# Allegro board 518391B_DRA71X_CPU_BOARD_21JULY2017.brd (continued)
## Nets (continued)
I2C4_SDA: R173.1 R178.1 U30.9(SDA) U33.1(I2C_SDA)
ICLINK_01_0: U34.43(ICP) U36.35(NVMISO)
ICLINK_01_1: U34.42(ICN) U36.36(NVMOSI)
ICLINK_01_2: U34.41(DIFSO) U36.37(VSSB)
ICLINK_01_3: U34.40(DICLKO) U36.38(NVSCLK)
IRQ_GNSS: U21.49(IRQ_GNSS) U27.Y1(MMC3_CMD/SPI3_SCLK/USB3_ULPI_D4)
ISFSN_CHIP_01: U34.32(ISFSN) U36.52(ISFSN)
ISFSP_CHIP_01: U34.33(ISFSP) U36.53(ISFSP)
LDOVANA: C458.1 U32.43(LDOVANA_OUT)
LDRV1: R20.2 U19.25(LDRV1)
LDRV2: R21.1 U19.21(LDRV2)
LIN_INH: TP53.1 U47.8(INH)
LIN_WAKE: TP48.1 U47.3(NWAKE)
MCU_CAN0_RX: U37.62(P10_0) U46.4(RXD)
MCU_CAN0_STB: R383.1 U37.29(P8_3) U46.8(STB)
MCU_CAN0_TX: U37.63(P10_1) U46.1(TXD)
MCU_CAN2_RX: RJ27.1 U37.10(P0_5)
MCU_CAN2_STB: RJ31.1 U37.28(P8_1)
MCU_CAN2_TX: RJ28.1 U37.9(P0_4)
MCU_DBG_RESETN: J15.13 R349.2
MCU_DCAN1_RX: R371.2 RJ27.3
MCU_DCAN1_STB: R426.2 RJ31.3
MCU_DCAN1_TX: R372.2 RJ28.3
MCU_FLMD0: J15.4 R332.1 U37.26(FLMD0)
MCU_FLMD1: J15.6 R322.1 R323.2
MCU_LIN_EN: R375.1 U37.30(P8_4) U47.2(EN)
MCU_P10_9: R327.2 U37.54(P10_9)
MCU_P10_10: R331.2 U37.55(P10_10)
MCU_P10_13: R335.2 U37.58(P10_13)
MCU_P10_14: R341.2 U37.59(P10_14)
MCU_PMIC_POWERHOLD: Q2.5(G2) R319.2 U37.31(P8_5)
MCU_RDY: J15.11 U37.14(JP0_5)
MCU_RESETN: C498.2 R345.1 R349.1 U37.20(RESET)
MCU_RLIN30RX: R356.2 U37.7(P0_3)
MCU_RLIN30TX: R357.2 U37.6(P0_2)
MCU_RLIN31RX: R374.2 U37.56(P10_11) U47.1(RXD)
MCU_RLIN31TX: U37.57(P10_12) U47.4(TXD)
MCU_SCL: R350.2 U37.1(P10_3) U38.6(SCL)
MCU_SDA: R351.2 U37.64(P10_2) U38.5(SDA)
MCU_SPI1_SI: R323.1 U37.53(P10_8)
MCU_TCK: J15.1 U37.17(JP0_2)
MCU_TDI: J15.7 R348.2 U37.19(JP0_0)
MCU_TDO: J15.5 U37.18(JP0_1)
MCU_TMS: R354.2 R391.1 U37.16(JP0_3)
MCU_TRSTN: R355.1 R377.1 U37.15(JP0_4)
MCU_TVD: J15.8 R376.1
MCU_WP: R347.1 U37.27(P8_0) U38.7(WP)
MCU_X1: C493.1 U37.25(X1) X1.2
MCU_X2: R130.2 U37.24(X2)
MDIO_MDCLK: U27.D10(VIN2A_D10/MDIO_MCLK/VOUT2_D13/K) U40.1(MDC)
MDIO_MDIO: R344.2 U27.C10(VIN2A_D11/MDIO_D/VOUT2_D12/KBD_) U40.36(MDIO)
MMC2_CLK: R99.1 R299.1 R300.2
MMC2_CMD: R295.2 U27.A6(GPMC_CS1/MMC2_CMD/GPMC_A22/VIN2) U31.P5(CMD)
MMC2_DAT0: R273.2 U27.D7(GPMC_A24/MMC2_DAT0/GPMC_A18/VIN) U31.K2(DAT0)
MMC2_DAT1: R271.2 U27.C6(GPMC_A25/MMC2_DAT1/GPMC_A19/VIN) U31.N2(DAT1)
MMC2_DAT2: R269.2 U27.A5(GPMC_A26/MMC2_DAT2/GPMC_A20/VIN) U31.K3(DAT2)
MMC2_DAT3: R291.2 U27.B6(GPMC_A27/MMC2_DAT3/GPMC_A21/VIN) U31.N3(DAT3)
MMC2_DAT4: R289.2 U27.A4(GPMC_A19/MMC2_DAT4/GPMC_A13/VIN) U31.N8(DAT4)
MMC2_DAT5: R272.2 U27.E7(GPMC_A20/MMC2_DAT5/GPMC_A14/VIN) U31.K8(DAT5)
MMC2_DAT6: R270.2 U27.D6(GPMC_A21/MMC2_DAT6/GPMC_A15/VIN) U31.N9(DAT6)
MMC2_DAT7: R268.2 U27.C5(GPMC_A22/MMC2_DAT7/GPMC_A16/VIN) U31.K9(DAT7)
MMC_PWR_ON: R412.2 U27.K23(GPIO6_16/MCASP1_AXR10/CLKOUT1/T) U70.3(ON)
NEO_RESETN: R238.2 U25.8(RESET_N) U27.H3(GPMC_A13/QSPI1_RTCLK/TIMER7/SPI)
NEO_TIMEPULSE: R68.2 R69.1 R79.2
NFAULT: D11.2(C) U27.H2(GPMC_BEN0/GPMC_CS4/VIN2B_DE1/VI) U28.26(FAULTN)
NMUTE: U27.K5(GPMC_A16/QSPI1_D0(I/O)/GPIO2_6) U28.25(MUTEN)
NSTANDBY: U27.K6(GPMC_A15/QSPI1_D2(I)/TIMER5/GPI) U28.24(STANDBYN)
NTRST: J14.9(NTRST) R312.2 RJ26.3
NWARN: D10.2(C) U27.H6(GPMC_BEN1/GPMC_CS5/VIN2B_CLK1/V) U28.27(WARNN)
OUT1M: C87.1 L12.1 U28.32(OUT_1M)
OUT1P: C93.1 L13.1 U28.34(OUT_1P)
OUT2M: C330.1 L55.1 U28.38(OUT_2M)
OUT2P: C371.1 L56.1 U28.40(OUT_2P)
OUT3M: C97.1 L14.1 U28.45(OUT_3M)
OUT3P: C107.1 L15.1 U28.47(OUT_3P)
OUT4M: C376.1 L57.1 U28.51(OUT_4M)
OUT4P: C400.1 L58.1 U28.53(OUT_4P)
PG1_PMIC: R127.1 R316.1 TP41.1(TP) U32.27(GPIO_6 [VRTC])
PG_LM5141: Q11.2(G2) R217.1 SW2.3(B2) TP12.1(TP) U18.21(PG) U42.6(EN)
PG_LM5175: C63.2 R40.2 R208.1 TP9.1(TP) U19.17(PGOOD) U43.3(IN) U51.3(IN)
PG_LM53603: R7.2 TP6.1(TP) U11.7(EN) U15.8(RESETN)
PM1_SCL: J21.36 R414.1 U71.2(I) U74.5(SCL)
PM1_SDA: J21.38 R415.1 U72.2(I) U74.4(SDA)
PM_BRD_PWR_OFF: J21.26 Q11.5(G2) R423.1
PM_RESETN: J21.28 R402.2
PMIC_ADCIN1: R115.1 U32.38(ADCIN1)
PMIC_ADCIN2: R112.1 U32.39(ADCIN2)
PMIC_BOOT: R106.2 R107.2 U32.16(BOOT [VRTC])
PMIC_EN: R433.2 SW2.1(A1) SW2.2(A2) U32.15(GPIO_5 [VRTC]) U39.3(ON)
PMIC_GPIO_2: TP35.1 U32.2(GPIO_2 [VIO_IN])
PMIC_GPIO_4: TP37.1 U32.1(GPIO_4 [VIO_IN])
PMIC_POWERHOLD: Q2.3(D2) R41.1 R422.1 SW2.4(B1)
PMIC_REGEN1_3V3_OD: R378.1 TP50.1(TP) U19.1(EN/UVLO) U20.3(ON) U32.12(GPIO_0 [VRTC]) U41.5(EN) U48.3(ON) U49.5(EN)
PMIC_SCLK_OUT: TP34.1 U32.48(SYNCCLKOUT [VRTC])
SD_CLK: R406.1 RU1.14(4B1)
SD_CMD: R405.1 RU1.11(3B1)
SD_D0: R407.1 RU2.2(1B1)
SD_D1: R408.1 RU2.5(2B1)
SD_D2: R403.1 RU1.2(1B1)
SD_D3: R404.1 RU1.5(2B1)
SIL_INTB_CHIP0: R313.1 U27.F3(GPMC_CS0/GPIO2_19) U36.39(INTM)
SIL_INTB_CHIP1: R122.1 U27.G4(GPMC_CS2/QSPI1_CS0/GPIO2_20/GPM) U34.19(INTB)
SIL_RSTB_CHIP0: R320.1 U27.L3(GPMC_A11/VIN1A_FLD0/VOUT3_FLD/V) U36.33(RSTB)
SIL_RSTB_CHIP1: R126.1 U27.G1(GPMC_A12/GPMC_A0/VIN1B_FLD1/TIM) U34.13(RSTB)
SWP1: J8.1 R258.2 SW1.1(A1)
SWP2: J8.3 R254.2 SW1.2(A2)
SWP3: J8.5 R250.2 SW1.3(A3)
SWP4: J8.7 R248.2 SW1.4(A4)
SWP5: J8.9 R244.2 SW1.5(A5)
SWP6: J8.11 R240.2 SW1.6(A6)
TAS_LRCLK_2INM: C100.1 R256.1 U28.14(FSYNC)
TAS_MCLK_3INM: C104.1 RJ29.2 U28.12(MCLK)
TAS_SCLK_2INP: C99.1 R257.1 U28.13(SCLK)
TAS_SDIN1A_1INP: C94.1 R253.1 U28.15(SDIN1)
TAS_SDIN2A_1INM: C95.1 R252.1 U28.16(SDIN2)
TAS_SYNC: RJ8.3 RJ9.2
TLIN1: J17.10 R154.2 U47.6(LIN)
TRD1_N: C233.1 J17.2
TRD1_P: C232.1 J17.1
TRD_N: L44.3 U40.13(TRD_N)
TRD_P: L44.4 U40.12(TRD_P)
TRSTPD: J14.8(TRSTPD) R330.1 RJ26.1
USB1_CS: C262.1 R10.1 R203.2 R204.1
USB1_DM: FL2.1 U11.14(DM_IN)
USB1_DP: FL2.4 U11.13(DP_IN)
USB1_IMON: C18.1 R6.1 R317.2 TP3.1(TP) U11.1(IMON)
USB1_STATUS: R2.1 U11.17(STATUS) U27.K22(GPIO6_15/MCASP1_AXR9/DCAN2_RX/U)
USB1_VBUS_OCN: R3.1 U11.18(FAULT) U27.H21(GPIO6_14/MCASP1_AXR8/DCAN2_TX/U)
USB2_DM: FL1.4 U12.5(VD-)
USB2_DP: FL1.1 U12.6(VD+)
USB_AC_TXN0: C14.2 FL6.4
USB_AC_TXP0: C13.2 FL6.1
VAUDIO_9V0: C191.1 C445.1 C484.1 C510.1 C528.1 C533.1 R293.1 R304.2 R314.1 R326.2 R352.1 R364.1 R366.2 R385.1 R392.2 R395.1 R399.2 TP45.1(TP) U44.16(OUT)
VBIAS_ERR: R135.2 U27.F6(GPMC_WAIT0/GPIO2_28/GPMC_A25/GP) U44.9(ERR)
VBIAS_SNS_SEL: R384.1 U27.N5(UART3_RXD/RMII1_CRS/MII0_RXDV/V) U44.7(SNS_SEL)
VCAM_9V0: C177.1 C234.1 C249.1 L51.2 R363.1 TP46.1(TP) U44.14(OUT2)
VCAP_VBBLDO_DSP: C388.1 U27.F8(CAP_VBBLDO_DSP)
VCAP_VBBLDO_GPU: C329.1 U27.T7(CAP_VBBLDO_GPU)
VCAP_VBBLDO_IVA: C395.1 U27.G14(CAP_VBBLDO_IVA)
VCAP_VBBLDO_MPU: C394.1 U27.F17(CAP_VBBLDO_MPU)
VCAP_VDDRAM_CORE1: C322.1 U27.U20(CAP_VDDRAM_CORE1)
VCAP_VDDRAM_CORE3: C358.1 U27.K7(CAP_VDDRAM_CORE3)
VCAP_VDDRAM_CORE4: C412.1 U27.G19(CAP_VDDRAM_CORE4)
VCAP_VDDRAM_DSP: C334.1 U27.L7(CAP_VDDRAM_DSP)
VCAP_VDDRAM_GPU: C320.1 U27.V7(CAP_VDDRAM_GPU)
VCAP_VDDRAM_IVA: C426.1 U27.G12(CAP_VDDRAM_IVA)
VCAP_VDDRAM_MPU: C374.1 U27.G18(CAP_VDDRAM_MPU)
VCNTL_3V3: C481.1 Q8.3(D2) R373.2 R378.2 U32.34(VIO_IN)
VDA_COREGMACVID_FIL1V8: C359.1 C372.1 E5.3 U27.K10(VDDA_DSP_IVA_1) U27.L9(VDDA_CORE_GMAC) U27.L10(VDDA_DSP_IVA_2)
VDA_CSI_FIL1V8: C324.1 C333.1 E3.3 U27.T6(VDDA_CSI)
VDA_DDRDBGGPUPER_FIL1V8: C340.1 C343.1 E4.3 U27.M10(VDDA_PER) U27.N9(VDDA_GPU) U27.N10(VDDA_DEBUG)
VDA_MPU_ABE_FIL1V8: C349.1 C407.1 E7.3 U27.K16(VDDA_MPU_ABE_1) U27.L16(VDDA_MPU_ABE_2)
VDA_OSC_FIL1V8: C286.1 C309.1 E1.3 U27.W13(VDDA_OSC_1) U27.Y13(VDDA_OSC_2)
VDA_PCIE_FIL1V8: C301.1 C308.1 C310.1 E2.3 U27.W11(VDDA_PCIE_1) U27.W15(VDDA_HDMI_1) U27.Y11(VDDA_PCIE_2) U27.Y15(VDDA_HDMI_2)
VDA_PHY_1V8: C302.1 C306.1 C465.1 E2.1 E3.1 U27.W8(VDDA_USB_1) U27.Y8(VDDA_USB_2) U27.Y9(VDDA_USB_3) U32.21(LDO2_OUT)
VDA_PLL_1V8: C331.1 C406.1 C443.1 E1.1 E4.1 E5.1 E6.1 E7.1 U27.R20(VDDA_DDR) U32.4(LDO5_OUT)
VDA_SDIO_DV: C345.1 C477.1 R226.1 R227.1 R228.1 R229.1 R230.1 R231.1 R410.1 U27.N8(VDDSHV8_1) U27.P8(VDDSHV8_2) U32.23(LDO1_OUT)
VDA_USB_3V3: C281.1 C284.1 C285.1 C440.1 R236.2 R237.1 U27.AA10(VDDA33V_USB_1) U27.Y10(VDDA33V_USB_2) U32.7(LDO4_OUT)
VDA_VIDEO_FIL1V8: C364.1 C408.1 E6.3 U27.K14(VDDA_VIDEO_1) U27.L14(VDDA_VIDEO_2)
VDISP_16V0: C146.1 C462.1 L20.2 TP47.1(TP) U43.5(OUT5) U43.6(OUT6) U43.7(OUT7)
VEXP_1V8A: J19.113 R171.2
VEXP_1V8B: J19.112 R170.2
VEXP_3V3A: J19.8 R188.1
VEXP_3V3B: J19.9 R187.1
VEXP_5V0A: J19.1 R186.1
VEXP_5V0B: J19.5 R185.1
VEXP_5V0C: J19.117 R167.2
VEXP_5V0D: J19.116 R166.2
VHDMI_5V0: C268.1 P1.18(+5V) U17.12(5V_OUT)
VIO_3V3: C44.1 C49.1 C57.1 C83.1 C114.1 C118.1 C119.1 C120.1 C128.1 C136.1 C137.1 C140.1 C141.1 C147.1 C148.1 C151.1 C152.1 C189.1 C207.1 C212.1 C260.1 C261.1 C264.1 C267.1 C275.2 C277.1 C282.1 C283.1 C287.1 C288.1 C296.1 C350.1 C353.1 C356.1 C435.1 C437.1 C442.2 C446.2 C451.1 C453.1 C455.2 C456.2 C457.2 C459.1 C461.1 C507.1 C508.1 C509.1 C511.1 C517.1 C518.1 C519.1 C539.2 C546.1 J21.1 J21.2 J21.3 L16.1 L17.2 L63.1 P9.30 P9.32 P9.34 P9.36 R2.2 R3.2 R27.2 R33.1 R40.1 R55.1 R68.1 R71.1 R105.1 R122.2 R135.1 R149.1 R158.1 R169.2 R178.2 R181.2 R189.1 R191.2 R200.1 R201.1 R206.1 R212.2 R215.2 R216.1 R233.2 R234.2 R239.2 R241.2 R242.2 R243.2 R247.2 R249.1 R250.1 R254.1 R258.1 R262.2 R274.1 R290.1 R297.1 R306.1 R307.1 R308.1 R310.1 R311.1 R312.1 R313.2 R328.1 R329.1 R334.1 R342.2 R344.1 R358.2 R360.2 R365.2 R412.1 RJ1.1 RJ6.3 RJ7.3 RJ8.1 RJ10.3 RJ13.1 RJ14.3 RJ16.1 RJ17.1 RJ18.3 RJ19.3 RJ20.3 RJ21.3 RJ22.3 RJ23.3 RJ24.3 RJ25.3 RU1.16(VCC) RU2.16(VCC) TP10.1(TP) U12.9(VIN) U13.5(VCC) U14.5(VCC) U17.23(VCCA) U20.7(VOUT2) U20.8(VOUT1) U21.19(VBAT) U22.8(VCC) U25.22(V_BCKP) U25.23(VCC) U27.G9(VDDSHV1_1) U27.G10(VDDSHV1_2) U27.G15(VDDSHV3_1) U27.G17(VDDSHV3_2) U27.H15(VDDSHV3_3) U27.H17(VDDSHV3_4) U27.J7(VDDSHV10_1) U27.J8(VDDSHV10_2) U27.J19(VDDSHV3_5) U27.K8(VDDSHV10_3) U27.K19(VDDSHV3_6) U27.M7(VDDSHV9_1) U27.M19(VDDSHV4_1) U27.N7(VDDSHV9_2) U27.N19(VDDSHV4_2) U31.F2(VCC.1) U31.F3(VCC.2) U31.F4(VCC.3) U31.F5(VCC.4) U31.F6(VCC.5) U31.F7(VCC.6) U31.F8(VCC.7) U31.F9(VCC.8) U34.24(VIO1) U34.27(VIO2) U36.44(VIO1) U36.47(VIO2) U40.11(VDDA) U40.22(VDDIO) U41.7(IN2) U41.8(IN1) U52.1(VCCIO.1) U54.5(VCC) U55.14(VCC) U56.14(VCC) U70.1(VIN.1) U70.2(VIN.2)
VIO_3V3_SD: C540.1 C541.1 C542.1 C544.1 C545.1 P10.4(VDD) U66.1(VCC) U67.1(VCC) U68.1(VCC) U70.7(VOUT.2) U70.8(VOUT.1)
VMEDIA_16V0: J17.7 J17.8 TP62.1(TP) U51.5(OUT5) U51.6(OUT6) U51.7(OUT7)
VOSNS: C66.2 R47.2 U19.12(VOSNS)
VOUT3_INTB: R237.2 U27.AC10(WAKEUP0/DCAN1_RX/GPIO1_0/SYS_NI) U30.31(INTB)
VOUT3B_CLK: R73.1 U30.10(PCLK)
VOUT3B_D0: J8.2 R259.1 R417.2 SW1.12(B1) U27.F1(GPMC_AD0/VIN1A_D0/VOUT3_D0/GPIO) U30.43(B0/O4)
VOUT3B_D1: J8.4 R255.1 R418.2 SW1.11(B2) U27.E2(GPMC_AD1/VIN1A_D1/VOUT3_D1/GPIO) U30.44(B1/O5)
VOUT3B_D2: J8.6 R251.1 R419.2 SW1.10(B3) U27.E1(GPMC_AD2/VIN1A_D2/VOUT3_D2/GPIO) U30.45(B2)
VOUT3B_D3: J8.8 R247.1 R413.2 SW1.9(B4) U27.C1(GPMC_AD3/VIN1A_D3/VOUT3_D3/GPIO) U30.46(B3)
VOUT3B_D4: J8.10 R243.1 R420.2 SW1.8(B5) U27.D1(GPMC_AD4/VIN1A_D4/VOUT3_D4/GPIO) U30.47(B4)
VOUT3B_D5: J8.12 R241.1 R421.2 SW1.7(B6) U27.D2(GPMC_AD5/VIN1A_D5/VOUT3_D5/GPIO) U30.48(B5)
VOUT3B_D6: RJ25.2 U27.B1(GPMC_AD6/VIN1A_D6/VOUT3_D6/GPIO) U30.1(B6)
VOUT3B_D7: RJ24.2 U27.B2(GPMC_AD7/VIN1A_D7/VOUT3_D7/GPIO) U30.2(B7)
VOUT3B_D8: RJ17.2 U27.C2(GPMC_AD8/VIN1A_D8/VOUT3_D8/GPIO) U30.35(G0/IO2)
VOUT3B_D9: RJ16.2 U27.D3(GPMC_AD9/VIN1A_D9/VOUT3_D9/GPIO) U30.36(G1/IO3)
VOUT3B_D10: RJ20.2 U27.A2(GPMC_AD10/VIN1A_D10/VOUT3_D10/G) U30.37(G2)
VOUT3B_D11: RJ21.2 U27.B3(GPMC_AD11/VIN1A_D11/VOUT3_D11/G) U30.38(G3)
VOUT3B_D12: RJ19.2 U27.C3(GPMC_AD12/VIN1A_D12/VOUT3_D12/G) U30.39(G4)
VOUT3B_D13: RJ22.2 U27.C4(GPMC_AD13/VIN1A_D13/VOUT3_D13/G) U30.40(G5)
VOUT3B_D14: RJ18.2 U27.A3(GPMC_AD14/VIN1A_D14/VOUT3_D14/G) U30.41(G6)
VOUT3B_D15: RJ23.2 U27.B4(GPMC_AD15/VIN1A_D15/VOUT3_D15/G) U30.42(G7)
VOUT3B_D16: U27.M1(GPMC_A0/VIN1A_D16/VOUT3_D16/VIN) U30.25(R0/IO0)
VOUT3B_D17: U27.M2(GPMC_A1/VIN1A_D17/VOUT3_D17/VIN) U30.26(R1/IO1)
VOUT3B_D18: U27.L2(GPMC_A2/VIN1A_D18/VOUT3_D18/VIN) U30.27(R2)
VOUT3B_D19: U27.L1(GPMC_A3/QSPI1_CS2/VIN1A_D19/VOU) U30.28(R3)
VOUT3B_D20: U27.K3(GPMC_A4/QSPI1_CS3/VIN1A_D20/VOU) U30.29(R4)
VOUT3B_D21: U27.K2(GPMC_A5/VIN1A_D21/VOUT3_D21/VIN) U30.32(R5)
VOUT3B_D22: U27.J1(GPMC_A6/VIN1A_D22/VOUT3_D22/VIN) U30.33(R6)
VOUT3B_D23: U27.K1(GPMC_A7/VIN1A_D23/VOUT3_D23/VIN) U30.34(R7)
VOUT3B_DE: U27.J2(GPMC_A10/VIN1A_DE0/VOUT3_DE/VIN) U30.5(DE)
VOUT3B_HSYNC: U27.K4(GPMC_A8/VIN1A_HSYNC0/VOUT3_HSYN) U30.3(HS)
VOUT3B_VSYNC: U27.H1(GPMC_A9/VIN1A_VSYNC0/VOUT3_VSYN) U30.4(VS)
VPOC_DISPLAY: C145.1 C454.1 L20.1 P2.2
VREF_DBG: J14.1(VREF_DBG) J14.12(VREF_TR) R308.2
VSW_3V3: C163.2 C176.1 R128.2 R129.2 TP42.1(TP) U35.10(VIN) U39.7(VOUT2) U39.8(VOUT1)
VSW_5V0: C237.1 C238.1 C269.1 C441.1 C527.1 R28.2 R30.2 R31.1 R166.1 R167.1 R185.2 R186.2 TP57.1(TP) U17.10(VCC5V) U32.8(LDO4_IN) U48.7(VOUT2) U48.8(VOUT1) U49.7(IN2) U49.8(IN1)
VSYS_3V3: C56.1 C59.1 C60.1 C64.1 C181.1 C188.1 C190.1 C194.1 C290.1 C444.1 C447.1 C450.1 C464.1 C469.1 C470.1 C474.1 C475.1 C478.2 C497.1 C500.2 C505.2 C521.1 C522.1 C548.1 C549.2 C554.2 L6.2 L34.1 Q8.4(S2) R22.2 R23.2 R41.2 R187.2 R188.2 R217.2 R319.1 R345.2 R347.2 R348.1 R350.1 R351.1 R354.1 R370.2 R374.1 R376.2 R414.2 R415.2 R416.1 U20.1(VIN1) U20.2(VIN2) U24.16(VCCB) U32.3(LDO5_IN) U32.5(LDO_IN) U32.10(SMPS3_IN) U32.18(SMPS4_IN) U32.22(LDO12_IN) U32.29(SMPS2_IN) U32.32(SMPS1_IN) U32.37(VCC_SENSE) U32.42(VCCA) U32.46(SMPS_IN) U37.8(EVCC_1) U37.23(REGVCC) U37.34(A0VREF) U37.60(EVCC_2) U38.8(VCC) U39.1(VIN1) U39.2(VIN2) U42.4(ILM) U42.8(VIN) U45.5(VIO/NC) U46.5(VIO/NC) U71.5(VCC) U72.5(VCC) U74.6(VS) U76.4(VDD)
VSYS_5V0: C203.1 C204.1 C220.1 C222.1 C514.1 C515.1 R140.2 R143.2 TP51.1(TP) U18.16(VCCX) U20.4(VBIAS) U39.4(VBIAS) U42.2(VOUT) U45.3(VCC) U46.3(VCC) U48.1(VIN1) U48.2(VIN2) U48.4(VBIAS) U70.4(VBIAS)
VSYS_10V5: C214.1 C247.1 C248.1 L54.2 R172.2 TP55.1(TP) U19.24(BIAS) U44.1(IN) U44.2(EN1) U44.3(EN2)
VSYS_16V0: C10.2 C11.1 C16.2 C33.1 C34.1 C35.1 C231.1 C250.1 C253.1 C266.2 C538.1 J13.1 Q7.5(D) R46.2 R47.1 R182.1 TP7.1(TP) U15.12(VIN1) U15.13(VIN2) U43.8(VS8) U43.9(VS9) U43.10(VS10) U50.7(VIN) U51.8(VS8) U51.9(VS9) U51.10(VS10)
VTT_DDR: C144.2 C154.2 C156.2 C158.2 C413.1 C414.1 C415.1 C417.1 C418.1 C419.1 C420.1 C421.1 C422.1 C423.1 C424.1 C425.1 R83.1 R84.1 R85.1 R86.1 R87.1 R88.1 R89.1 R90.1 R91.1 R92.1 R93.1 R95.1 R96.1 R120.2 R276.1 R277.1 R279.1 R280.1 R281.1 R282.1 R283.1 R284.1 R285.1 R286.1 R287.1 R288.1 U35.3(VO)
VTUN_1V8: C138.1 C139.1 C149.1 C150.1 C205.1 C452.1 C460.1 L36.2 TP52.1(TP) U34.25(VD) U36.45(VD)
VTUN_1V8_OUT: C206.1 R137.1 RJ12.3 U41.1(OUT1) U41.2(OUT2)
VTUN_3V3: C169.2 C170.2 C179.2 C180.2 C235.1 C494.2 C501.2 L52.2 R153.2 R162.2 TP56.1(TP) U34.12(VA) U36.18(VA)
VTUN_3V3_OUT: C236.1 R150.1 RJ13.3 U49.1(OUT1) U49.2(OUT2)
VUSB_5V0: C12.1 C15.1 C17.1 C19.1 C20.1 C25.1 C262.2 C263.1 L3.2 R7.1 R198.1 R203.1 R210.2 TP2.1(TP) U11.2(IN#2) U11.3(IN#3) U12.14(VBUS_SYS#14) U12.15(VBUS_SYS#15)
W_MMC1_CLK: RU1.13(4B2) U21.46(SDIO_CLK)
W_MMC1_CMD: RU1.10(3B2) U21.44(SDIO_CMD)
W_MMC1_D0: RU2.3(1B2) U21.43(SDIO_D0)
W_MMC1_D1: RU2.6(2B2) U21.41(SDIO_D1)
W_MMC1_D2: RU1.3(1B2) U21.40(SDIO_D2)
W_MMC1_D3: RU1.6(2B2) U21.42(SDIO_D3)
WL_EN: R223.2 U21.9(WL_EN) U27.AB1(MMC3_DAT7/SPI4_CS0/UART10_RTSN/)
WLAN_IRQ: U21.17(WLAN_IRQ) U27.Y2(MMC3_CLK/USB3_ULPI_D5/VIN2B_D7/)
XTAL1: U36.6(XTALI) X2.1(Y1)
XTAL2: U36.5(XTALO) X2.3(C1)
N00722: J21.8 R417.1
N00756: J21.9 R418.1
N00790: J21.10 R419.1
N00824: J21.11 R413.1
N00858: J21.12 R420.1
N00866: J21.13 R421.1
N00972: J21.32 R424.1
N01913: J20.1 U71.4(O) U73.4(IO3)
N01957: Q11.6(D2) R416.2 U71.1(OE) U72.1(OE)
N02093: C136.2 C137.2 C138.2 C139.2 C140.2 C141.2 C451.2 C452.2 C453.2 U36.46(DBYP)
N02103: J20.2 U72.4(O) U73.5(IO4)
N04059: J12.1 U36.55(DEBUGP)
N04077: J12.3 U36.54(DEBUGN)
N04157: U36.58(DOUT1) U56.5(2A)
N04169: U36.61(DOUT0) U56.2(1A)
N04588: C495.1 FB1.2 FB2.1
N04640: FB2.2 U36.4(CLKO)
N06498: R333.2 U36.80(ICN)
N09601: C179.1 C180.1 C501.1 U36.17(ABYP)
N10369: C178.2 U36.13(AMVAG)
N10535: C186.2 U36.7(DACREF)
N13716: J11.1 U34.35(DEBUGP)
N13723: J11.3 U34.34(DEBUGN)
N14506: C147.2 C148.2 C149.2 C150.2 C151.2 C152.2 C459.2 C460.2 C461.2 U34.26(DBBYP)
N19536: C169.1 C170.1 C494.1 U34.11(ABYP)
N22082: C196.2 C215.1 L37.2
N22086: C196.1 L29.2 U36.8(B3I)
N22133: C215.2 C223.1 L45.2
N22186: C223.2 C230.2 C251.1 D17.1 D18.1 L47.1 L53.1 R155.1 R156.1
N26490: C211.2 C221.1 C230.1 D13.1 L41.1 L47.2 R139.2
N26569: C198.2 C211.1 L41.2 R136.2 R139.1
N26753: C221.2 L50.2
N40192: C483.1 R324.2 R325.1
N40651: R324.1 U34.48(XTALI)
N49875: C198.1 R136.1 U36.12(AMI)
N62214: U36.51(ZIFIOUT) U56.9(3A)
N62220: U36.49(ZIFQOUT) U56.12(4A)
N62232: U34.30(ZIFCLK) U55.5(2A)
N62244: U34.28(ZIFFS) U55.12(4A)
N62516: U34.31(ZIFIOUT) U55.2(1A)
N62529: U34.29(ZIFQOUT) U55.9(3A)
N65146: C213.1 L45.1
N65896: C195.1 L37.1
N69340: C224.1 L48.1
N69344: C219.1 L46.1
N70553: C187.1 C197.1 L30.2 U36.10(FMI)
N70759: C197.2 L39.2
N70763: C229.1 L39.1 L46.2 L48.2
N71180: C229.2 L53.2
N74538: C251.2 J18.1
N75523: C252.1 C254.1 D18.2 R156.2 R162.1
N16778201: P10.9(INSERT) R411.2 U69.5(IO2)
N16778260: P10.10(INSERT_COM) R409.1
N16778400: C543.1 U69.1(VCC)
N16778910: C547.1 U70.6(CT)
N16783560: Q11.3(D2) R422.2
N22073312: R299.2 U31.P6(CLK)
N22234321: R266.2 U27.G21(I2C2_SCL/HDMI1_DDC_SDA)
N22234323: R265.2 U27.F23(I2C2_SDA/HDMI1_DDC_SCL)
N22235146: R103.2 U27.C16(MCASP1_ACLKX/VIN1A_FLD0/I2C3_SD)
N26762656: R216.2 U17.4(LS_OE)
N26762977: R33.2 U17.11(CT_HPD)
N26765506: C526.1 R151.2 R389.1
N27139839: R264.1 U27.J20(TDO/GPIO8_28)
N27139840: R70.1 U27.K25(RTCK/GPIO8_29)
N27143875: R72.1 U27.J25(XREF_CLK0/MCASP2_AXR8/MCASP1_AX)
N27143876: R74.1 U27.J24(XREF_CLK1/MCASP2_AXR9/MCASP1_AX)
N27143878: R75.1 U27.H25(XREF_CLK3/MCASP2_AXR11/MCASP1_A)
N27144522: R66.2 U27.U3(MMC1_CLK/GPIO6_21)
N27225962: R292.1 U27.E14(EMU2)
N27305837: R100.2 U27.B16(MCASP1_AXR10/MCASP6_ACLKX/MCASP)
N27305901: R102.2 U27.E16(MCASP1_AXR14/MCASP7_ACLKX/MCASP)
N27306016: R98.2 U27.A22(MCASP3_ACLKX/MCASP3_ACLKR/MCASP)
N27380264: J14.15(TGT_DETECT) R309.2
N27473363: R25.2 U17.3(HPD_A)
N29751222: C81.1 U52.16(3V3OUT)
N29751238: C73.1 C78.1 L9.2 U52.19(VCC)
N29751250: C71.1 J7.1(USBVDD) L9.1 R51.2
N29751338: C72.1 R51.1 R52.1 U52.18(RESET#)
N29751389: R55.2 U52.11(CBUS3)
N29751493: R232.2 U52.30(TXD)
N29756671: C242.1 D16.2(A) D19.1(K) U47.7(VSUP)
N29756747: D16.1(K) R154.1
N29757886: C525.1 R152.1 R388.2
N29757942: R382.1 RJ31.2 U45.8(STB)
N29776322: C228.1 C239.1 L40.2 L51.1 R138.2
N29776336: L27.2 L40.1 R132.2 R138.1
N29776342: L27.1 L62.2 R132.1
N29776461: C162.1 U33.41(RIN0+)
N29776463: C162.2 L60.1 P5.1
N29776467: C159.1 U33.42(RIN0-)
N29776493: C159.2 R114.1
N29818953: C496.1 U37.22(AW0VCL)
N29819003: C482.2 U37.49(ISOVCL)
N29842389: C133.1 C466.1 C488.1 L63.2 U33.7(VDDIO#7) U33.29(VDDIO#29)
N29842691: FL9.2 P2.1
N29842700: FL9.3 P2.3
N29844838: C400.2 U28.54(BST_4P)
N29844877: C376.2 U28.50(BST_4M)
N29844974: C107.2 U28.48(BST_3P)
N29845018: C97.2 U28.44(BST_3M)
N29845137: C371.2 U28.41(BST_2P)
N29845191: C330.2 U28.37(BST_2M)
N29845296: C93.2 U28.35(BST_1P)
N29845351: C87.2 U28.31(BST_1M)
N29845492: RJ7.2 U28.22(I2C_ADDR0)
N29845506: RJ6.2 U28.23(A2C_ADDR1)
N29845705: D11.1(A) R242.1
N29845767: D10.1(A) R239.1
N29847308: R339.2 R340.1 U33.35(IDX)
N29847310: R337.1 R338.2 U33.37(MODE)
N29886815: C121.1 U28.5(VREG)
N29886820: C115.2 U28.6(VCOM)
N29886879: C112.1 R78.1 U28.8(AVDD)
N29886909: C112.2 C113.2 R80.2
N29887154: C115.1 R80.1 R82.2
N29887202: C121.2 R82.1 U28.4(AREF)
N29904430: RJ10.2 U28.18(GND5)
N29907236: RJ8.2 U28.19(VDD)
N29907619: C113.1 U28.7(AVDD_GND)
N29927099: C499.1 R130.1 X1.1
N29928016: R343.2 U38.1(A0)
N29951925: RJ28.2 U45.1(TXD)
N29951934: RJ27.2 U45.4(RXD)
N30013202: R79.1 U27.H24(XREF_CLK2/MCASP2_AXR10/MCASP1_A)
N30028770: RJ4.3 U25.11(RF_IN)
N30028774: TP21.1(TP) U25.14(LA_EN)
N30028852: TP29.1(TP) U25.1(SAFEBOOT_N)
N30028946: C79.2 J6.1 L11.2
N30028952: C79.1 L10.2 RJ4.2
N30028958: RJ4.1 U21.55(GNSS_ANT)
N30029070: TP19.1(TP) U21.48(BT_UART_DBG)
N30029300: U21.27(SLOW_CLK) Y1.3(OUT)
N30029334: TP11.1(TP) U21.25(EXT_LNA_EN_GNSS)
N30029342: DPX1.6(2.4GHZ) U21.65(2.4G_ANT)
N30029362: ANT1.1(ANT) C61.2 L8.2
N30029368: C61.1 DPX1.2(ANT) L7.2
N30029382: DPX1.4(5GHZ) U21.68(WL_5G_ANT)
N30029436: TP8.1(TP) U21.13(WL_UART_DBG)
N30070759: Q1.3(D2) R200.2 U14.2(I)
N30070805: D1.1(CATHODE) Q1.5(G2) R196.2 R197.1
N30074897: R205.1 U12.16(IADJ)
N30074992: R206.2 TP4.1(TP) U12.10(FLT)
N30075038: Q2.6(D2) R198.2 U12.7(VEN)
N30075044: R199.2 U12.8(DEN)
N30079884: Q1.6(D2) R201.2 U13.2(I)
N30079928: D2.1(CATHODE) Q1.2(G2) R194.2 R195.1
N30095792: R346.2 U40.2(INT_N)
N30095794: TP49.1(TP) U40.16(CLK_OUT/GPIO_2)
N30098069: R249.2 U26.7(VREF2) U26.8(EN)
N30100305: R305.2 U33.8(PCLK/GPIO6)
N30121035: J15.3 R377.2
N30121052: J15.9 R391.2
N30127007: R81.1 U27.C24(SPI1_SCLK/GPIO7_7)
N30127010: R77.1 U27.G25(SPI2_SCLK/UART3_RXD/GPIO7_14)
N30127037: R97.2 U27.C23(MCASP4_ACLKX/MCASP4_ACLKR/SPI3_)
N30157685: L60.2 L61.1
N30157690: L61.2 L62.1
N30189410: C259.1 J3.8 R190.2 R191.1 U1.7(RST)
N30229067: R306.2 U33.4(OSS_SEL/XOUT)
N30256264: R64.1 U23.L8(ZQ)
N30256273: R76.1 U29.L8(ZQ)
N30257754: C160.2 R117.1 R118.2 U35.1(REFIN)
N30258027: R128.1 U35.7(EN)
N30258029: R129.1 U35.9(PGOOD)
N30258277: C161.2 R120.1 U35.5(VOSNS)
N30258482: C416.1 R94.1 R278.1
N30260935: C463.1 R107.1 U32.44(LDOVRTC_OUT)
N30260943: C467.1 U32.40(VBG)
N30411655: R235.1 TP18.1(TP) U22.7(WP)
N30424134: C225.1 U44.4(VCC)
N30424229: C226.1 R380.1 U44.5(SNS_1)
N30424257: R362.1 U44.10(LIM1)
N30488156: C209.2 C217.2 C240.1 D14.1 D15.1 L38.1 L49.1 R144.1 R145.1
N30488160: C200.2 C209.1 L33.2
N30488166: C183.2 C200.1 L28.2
N30488172: C183.1 L25.2 U34.2(D3I)
N30488204: C199.1 L33.1
N30488206: C182.1 L28.1
N30488307: C216.2 L49.2
N30488309: C216.1 L31.1 L35.2 L42.2
N30488319: C184.2 L31.2
N30488321: C175.1 C184.1 L26.2 U34.4(FMI)
N30488353: C185.1 R131.1 U34.6(AMI)
N30488365: C201.1 L35.1
N30488367: C210.1 L42.1
N30488419: C192.2 C202.1 C217.1 D12.1 L32.1 L38.2 R133.2
N30488423: C185.2 C192.1 L32.2 R131.2 R133.1
N30488512: C202.2 L43.2
N30488558: C243.1 C244.1 D15.2 R145.2 R153.1
N30489215: C240.2 J16.1
N30489499: C168.2 U34.7(AMVAG)
N30491879: C276.2 C292.2 U27.AA12(VSSA_OSC0) Y3.2(GND1) Y3.4(GND2)
N30491883: C292.1 U27.Y12(XI_OSC0) Y3.3(C1)
N30491911: C276.1 U27.AB12(XO_OSC0) Y3.1(Y1)
N30492439: C506.1 U40.5(XI) Y2.3(C1)
N30492465: C503.1 U40.4(XO) Y2.1(Y1)
N30512853: C232.2 L44.1
N30512862: C233.2 L44.2
N30525930: R183.2 U27.P4(RGMII0_TXD3/RMII0_CRS/MII0_CRS/)
N30646408: R367.1 U44.11(LIM2)
N30646808: R364.2 R369.1 U44.15(FB1)
N30646826: R363.2 R368.1 U44.13(FB2)
N30649045: R381.1 U44.8(SNS_EN)
N30649515: C227.1 R379.1 U44.6(SNS_2)
N30674781: J10.1 R105.2 U33.5(OEN/XIN/REFCLK)
N30703324: C7.1 R1.2 U11.12(BIAS)
N30703458: R4.1 U11.19(ILIM_LO)
N30703463: R5.1 U11.20(ILIM_HI)
N30746595: RJ1.2 U11.10(OVP_SEL)
N30797231: C62.1 U20.6(CT)
N30798114: C245.1 U48.6(CT)
N30808408: L34.2 U42.7(SW)
N30809211: C220.2 R140.1 R141.2 U42.3(FB)
N30811250: R177.1 R182.2 RJ15.2 U50.5(EN/SYNC)
N30811520: C256.1 U50.3(VCC)
N30812987: C255.1 U50.2(BOOT)
N30812990: C255.2 R163.1
N30812993: L54.1 R163.2 U50.1(SW)
N30813342: C257.1 R175.1 R176.1 U50.4(FB)
N30813649: C257.2 R172.1 R175.2
N30818369: R148.2 R149.2 U43.14(STN)
N30818430: R147.2 U43.13(CL)
N30818444: R146.2 U43.12(DIAG_EN)
N30819162: R158.2 R159.2 U51.14(STN)
N30819197: R159.1 TP58.1(TP)
N30819223: R160.2 U51.13(CL)
N30819237: R161.2 U51.12(DIAG_EN)
N30821669: R143.1 U42.5(PG)
N31193882: Q6.4(G) R14.1
N31194203: Q4.4(G) R20.1
N31194290: Q5.4(G) R21.2
N31194295: Q7.4(G) R15.2
N31194655: D9.1(CATHODE) R42.1
N31194670: C67.1 R42.2 U19.2(VIN)
N31194787: C50.1 D8.1(K) U19.26(BOOT1)
N31194818: C47.2 D4.1(CATHODE) D6.1(K) U19.20(BOOT2)
N31196095: C55.2 R37.1 U19.15(CSG)
N31196104: C55.1 R38.1 U19.16(CS)
N31196146: C74.1 U19.7(SLOPE)
N31196169: R54.1 U19.5(DTH)
N31196187: C76.2 R50.1 U19.6(RT/SYNC)
N31196205: R48.1 R53.1 U19.4(MODE)
N31196259: C69.1 R44.2 U19.9(COMP)
N31196266: C68.1 R44.1
N31197066: C75.1 U19.8(SS)
N31197134: C70.2 R45.2 U19.3(VISNS)
N31197473: R43.2 R46.1 TP14.1(TP)
N31206842: Q3.4(G) U16.2(GT PULL DWN) U16.6(GATE DRV)
N31206856: C30.1 U16.1(VCAPL)
N31206860: C30.2 U16.7(VCAPH)
N31206880: C21.1 C22.1 L4.1 L5.1 Q3.5(D1) R202.2 U16.8(CATHODE)
N31207093: D21.2(ANODE) D22.2(ANODE)
N31207095: DS1.2(ANODE) R202.1
N31208453: R213.2 U18.13(HO)
N31208462: R214.1 U18.14(HOL)
N31208471: R219.2 U18.8(LO)
N31208480: R220.1 U18.7(LOL)
N31208503: Q10.4(G) R219.1 R220.2
N31208524: Q9.4(G) R213.1 R214.2
N31208551: C39.1 C270.2 D23.1(CATHODE) L6.1 Q9.1(S) Q10.5(D) R18.1 U18.12(SW)
N31208672: C39.2 D5.1(CATHODE) U18.11(HB)
N31208960: C270.1 R225.1
N31209649: C36.2 R18.2 R428.1 U18.18(CS)
N31209654: C36.1 R22.1 R428.2 U18.17(VOUT)
N31222073: C48.2 R218.1 R401.1 U18.23(EN)
N31222132: C41.2 R29.1
N31222198: C40.1 R29.2 U18.20(COMP)
N31222241: C51.2 U18.24(RES)
N31222246: C43.2 U18.22(SS)
N31222265: R35.1 R36.2 U18.6(OSC)
N31222285: C54.2 R34.1 U18.5(DITH)
N31222303: R222.2 U18.4(RT)
N31222717: R23.1 R24.2
N31223527: L3.1 R16.2 R209.1 R211.1 U15.1(SW1) U15.2(SW2)
N31223584: C27.1 R210.1 U15.5(BIAS)
N31223889: C26.2 R16.1
N31224124: R204.2 R207.1 U15.9(FB)
N31225374: R10.2 U11.6(CS)
N31225630: R208.2 U15.11(EN)
N31225660: R17.1 RJ2.2 U15.6(SYNC)
N31226612: C28.2 U15.4(VCC) U15.7(FPWM)
N31272257: R59.2 U24.2(1DIR) U24.3(2DIR)
N31313642: R8.2 U11.8(CTL1)
N31313645: R9.2 U11.9(CTL2)
N31432046: R148.1 TP54.1(TP)
N31435823: R317.1 U37.44(AP0_0)
N31460069: Q8.5(G2) Q8.6(D1) R370.1
N31485198: R67.1 U25.21(RXD_SPI_MOSI)
N31485201: R65.1 U25.20(TXD/SPI_MISO)
N31485220: R69.2 U25.3(TIMEPULSE)
N31486138: RJ5.2 U75.2(I)
N31555915: C265.1 R209.2 R211.2
N31573832: C208.1 C516.1 L36.1 RJ12.2
N31594961: C206.2 R137.2 R142.2 U41.3(FB/SNS)
N31595589: C218.1 U41.6(NR)
N31598114: C241.1 C524.1 L52.1 RJ13.2
N31598152: C246.1 U49.6(NR)
N31598156: C236.2 R150.2 R157.2 U49.3(FB/SNS)
N31635389: C534.2 C535.2 P8.2(TIP) R399.1 U65.1(IO)
N31635587: C531.2 C532.1 P8.3(RING) R395.2 R396.2 U64.1(IO)
N31636337: C529.2 C530.2 P7.2(TIP) R392.1 U63.1(IO)
N31636510: C520.2 C523.1 P7.3(RING) R385.2 R386.2 U62.1(IO)
N31636885: C512.2 C513.2 P6.2(TIP) R366.1 U61.1(IO)
N31637058: C502.2 C504.1 P6.3(RING) R352.2 R353.2 U60.1(IO)
N31637886: C489.2 C490.2 P4.2(TIP) R326.1 U59.1(IO)
N31638056: C473.2 C476.1 P4.3(RING) R314.2 R315.2 U58.1(IO)
N31638108: C448.2 C449.2 P3.2(TIP) R304.1 U57.1(IO)
N31638278: C438.2 C439.1 P3.3(RING) R293.2 R294.2 U53.1(IO)
N31691908: R57.1 TP20.1(TP) U24.10(2B2)
N31691918: R58.1 R60.1 TP22.1(TP) U24.12(1B2)
N31691928: R61.1 R62.1 TP23.1(TP) U24.13(1B1)
N31691937: R63.1 TP24.1(TP) U75.4(O)
N31730797: C8.1 D3.CATHODE L1.1
N31767762: R316.2 U37.43(AP0_1)
N31975868: TP32.1(TP) U27.F20(RSV_VPP)
N32186036: C174.1 U39.6(CT)
N32241906: J19.119 R168.1
N32242118: J19.22 RJ30.3
N32242181: J19.32 TP61.1(TP)
N32242306: J19.77 R165.1
N32242319: D20.1(A) R169.1
N32242321: D20.2(C) J19.45
N32242323: J19.76 TP59.1(TP)
N32242357: J19.73 R164.1
N32242411: J19.57 R184.1
N32256405: J19.47 RJ14.2
N32396399: TP38.1(TP) U33.47(PASS)
N32396462: C492.2 R336.2 TP43.1(TP)
N32396466: C491.2 R336.1 TP44.1(TP)
N32396489: C491.1 U33.39(CMLOUTN)
N32396498: C492.1 U33.38(CMLOUTP)
N32412234: R110.2 U33.43(MIPI_SEL) U33.46(SEL)
N32413360: J19.24 R180.2
N32413363: J19.25 R179.2
N32592449: R267.2 U27.E19(MCASP2_ACLKX/VIN1A_D7/PR2_MII0_)
N32593135: R99.2 U27.B5(GPMC_A23/MMC2_CLK/GPMC_A17/VIN2)
N32593759: R73.2 U27.G3(GPMC_CS3/QSPI1_CS1/VIN1A_CLK0/V)
N32595277: C375.2 R262.1 R263.1 R402.1 U27.K24(RESETN)
N32733566: R274.2 R275.1 U30.24(MODE_SEL)
N32807371: C129.1 U30.14(CAPP12)
N32807372: C131.1 C132.1 U30.7(CAPL12)
N32807373: C127.1 U30.17(CAPHS12)
N32830609: R427.1 TP67.1(TP) U24.11(2B1)
N32837329: C410.1 U30.23(CMF)
N32856854: C124.1 U30.20(DOUT+)
N32867532: C125.1 U30.19(DOUT-)
N32916975: R297.2 R298.1 U30.6(IDX)
N33050083: R429.2 U27.AC3(MCASP5_ACLKX/MCASP5_ACLKR/SPI4_)
N33095449: Q12.3(D2) R433.1 U76.3(RESETN)
N33095497: C553.1 D24.1(CATHODE) Q12.2(G2) R431.1 R432.1 U76.5(SENSE)
N33095499: Q12.5(G2) Q12.6(D2) R430.1
N33164061: C123.1 R290.2 U30.21(PDB)
N312234419: C26.1 U15.3(CBOOT)
N3026308320: R101.2 U27.B11(VIN2A_D12/RGMII1_TXC/VOUT2_D11/)

Pads without a net: ANT1 3 4; J2 5 6 8 9; J3 4 6 7 9 10; J7 4; J14 10 11 14 18 20 22 24 26 28 30 32 34 36 38 40 42 44 46 48 50 52 54 55 56 59 60; J15 10; J17 9 13 14; J19 2 7 10 26 27 29 30 33 34 35 37 38 39 41 42 44 48 49 50 51 53 54 55 56 67 68 70 71 72 78 94 95 96 97 99 100 101 102 103 105 106 107 108 110 111 114 120; J20 4 5; J21 4 5 6 14 15 17 18 19 20 21 22 23 24 27 30 31 33 35 37 39; NOREF#2 1; NOREF#5 1; NOREF#10 1; NOREF#11 1; NOREF#14 1; NOREF#15 1; NOREF#16 1; NOREF#17 1; P1 14; P3 4; P4 4; P6 4; P7 4; P8 4; P9 1 3 6 8 10 17 18 19 20 21 22 23 25 26 27 28 29 31 33 35 37 39; P10 11 12 13 14 15; RU2 11 12 13 14; U1 3 4 5; U12 1; U13 1; U14 1; U15 14; U16 3 5; U17 14 15 16 17 19 20 21 22; U21 3 4 11 12 15 16 21 22 23 24 29 30 31 32 36 37 38 39 58; U23 J1 J9 L1 L9; U25 2 4 5 6 9 15 16 17 18 19; U27 AA11 AB9 AC8 AD7 AD9 AE6 AE8 G20 K20 L19 T1 T2 T3 U1 U2 U4; U29 J1 J9 L1 L9; U30 11 12 13 16; U31 A1 A2 A9 A10 B1 B10 D2 D3 D4 D5 D6 D7 D8 D9 E2 E3 E5 E6 E7 E8 E9 H4 H5 H6 H7 J2 J3 J4 J6 J7 J8 J9 K4 K5 K6 K7 L5 L6 M2 M3 M6 M8 M9 N4 N5 N6 N7 P4 P7 T1 T10 U1 U2 U9 U10; U32 6 24 45 47; U33 11 12 13 14 25 26 27 28 32 33; U34 1 3 5 8 9 10 44 45 47; U36 2 3 9 11 14 15 16 19 20 21 22; U37 2 3 4 5 11 13 32 35 36 37 38 39 40 41 42 45 46 47 48 51 52; U40 6 9 14 17 18 19 20 21 34 35; U43 1 4 11; U51 1 4 11; U52 3 5 6 7 8 9 10 12 13 21 22 23 25 27 28 29 31 32; U66 2; U67 2; U68 2; U69 2 3; U73 1 3; U74 3; U76 1; Y1 1

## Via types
v1: diameter 0.406, hole 0.203, TOP to BOTTOM, 252 vias
v2: diameter 0.508, hole 0.254, TOP to BOTTOM, 2877 vias
v3: diameter 0.61, hole 0.305, TOP to BOTTOM, 48 vias
v4: diameter 0.457, hole 0.203, TOP to BOTTOM, 286 vias
v5: diameter 0.635, hole 0.305, TOP to BOTTOM, 91 vias

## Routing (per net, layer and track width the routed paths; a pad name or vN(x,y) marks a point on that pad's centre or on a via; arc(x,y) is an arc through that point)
1V8_I2C1_SCL: length 26.2
  TOP w0.127: v2(155.83,101.73) 155.84,101.73 U21.52 ; v2(148.84,88.27) 148.6,88.02 U26.3
  LY3 w0.133: v2(156.59,94.74) 155.07,93.22 v2(149.1,93.22)
  LY4 w0.133: v2(149.1,93.22) 149.34,92.98 149.34,91.68 148.84,91.19 v2(148.84,88.27) ; v2(156.59,94.74) 156.59,98.93 155.83,99.69 v2(155.83,101.73)
  BOTTOM w0.127: P9.2 156.71,94.62 v2(156.59,94.74) ; v2(148.84,88.27) R245.2
1V8_I2C1_SDA: length 27.4
  TOP w0.127: U26.4 148.1,88 v2(147.83,88.27) ; U21.50 v2(153.84,101.6)
  LY3 w0.133: v2(148.84,92.46) 155.11,92.46 v2(156.63,93.98)
  LY4 w0.133: v2(153.84,101.6) 153.84,99.91 155.32,98.42 155.32,95.25 156.59,93.98 v2(156.63,93.98) ; v2(148.84,92.46) 148.84,91.82 148.46,91.44 148.46,88.9 v2(147.83,88.27)
  BOTTOM w0.127: v2(147.83,88.27) R246.2 ; P9.4 156.77,94.12 v2(156.63,93.98)
1V8_RSTOUTN: length 71.1
  TOP w0.305: U31.M5 v2(123.21,62.41)
  LY3 w0.133: v2(159.26,74.42) 156.84,72.01 152.27,72.01 151.64,71.37 151.64,66.8 146.95,62.11 143.63,62.11 143,62.74 137.67,62.74 137.16,62.23 123.39,62.23 v2(123.21,62.41) 122.78,61.99 121.91,61.99 121.67,62.23 117.86,62.23 v2(117.47,61.85)
  LY4 w0.133: v2(159.26,74.42) 160.53,75.69 160.53,82.04 159.89,82.68 v2(159.89,89.79)
  BOTTOM w0.127: R296.1 123.44,62.65 v2(123.21,62.41) ; v2(159.89,89.79) 159.56,90.13 P9.14
  BOTTOM w0.14: U54.4 117.12,61.49 v2(117.47,61.85)
GND: length 1779.9
  TOP w0.203: R37.2 v2(62.61,120.14) ; U27.N20 U27.P19 ; U27.N17 U27.N16 U27.P15 ; U27.P11 U27.N12 ; U17.5 113.21,155.14 v2(113.16,155.19) ; U27.M16 U27.L15 U27.M14 U27.L13 U27.M12 ; U17.13 v2(117.57,153.13) ; U17.18 117.27,155.14 v2(117.6,154.81) ; U27.K13 U27.J14 ; U27.Y16 U27.AA15 ; U35.8 v2(62.86,47.24) ; U27.K11 U27.J10
  TOP w0.254: U27.H12 v1(93.94,81.78) U27.J12 ; U22.1 v2(40.64,97.28) ; v2(159,27.43) C227.2 C226.2 ; U27.T18 U27.U17 v1(90.69,87.63) ; U27.T18 v1(90.04,86.33) U27.R18 v1(89.39,86.33) U27.R19 v1(89.39,85.68) U27.P19 ; U27.T18 U27.U19 v1(88.74,87.63) U27.V19 89.31,88.2 v1(89.39,88.28) 89.31,88.37 U27.W19 ; U27.A1 v4(101.16,76.51) ; U30.15 v2(145.01,64.54) ; v2(44.2,83.69) C100.2 ; U27.U12 v1(93.94,86.98) U27.T12 ; U27.U12 U27.V11 U27.U10 95.02,87.2 95.02,86.77 U27.T10 ; U27.U12 U27.V13 U27.U14 ; U27.W9 v1(95.24,88.28) U27.V9 v1(95.89,88.28) U27.V8 ; U27.G16 v1(91.34,81.13) U27.H16 ; U27.N12 v1(93.94,84.38) U27.M12 ; U36.63 23.07,55.92 v2(23.28,56.13) 23.57,55.85 U36.62 ; U27.U14 U27.V15 U27.U16 ; U27.U14 v1(92.64,86.98) U27.T14 ; U22.4 v2(40.64,101.09) ; v1(93.29,91.53) 92.97,91.21 U27.AC13 ; U27.Y17 v1(90.69,88.93) U27.Y16 ; U27.AB11 93.94,90.88 v1(93.94,90.88) U27.AC11 ; v2(57.71,87.78) 57.72,87.77 C91.2 ; v2(77.98,62.23) 77.98,63.61 C126.2 ; R19.2 v2(53.59,129.03) ; v2(61.98,52.07) 62.36,51.68 U35.4 ; U27.G13 U27.H14 ; U25.7 v2(168.39,89.39) ; U27.U16 v1(91.34,86.98) U27.T16 ; U27.U16 v1(90.69,87.63) ; C225.2 v2(153.86,27.43) ; U25.10 v2(168.39,94.59) ; U27.A25 85.16,76.51 85.18,76.49 v4(85.18,76.36) ; U27.V17 v1(90.69,87.63) ; 28.57,40 28.57,38.86 28.83,38.61 ; v2(50.86,81.67) C98.2 v2(48.45,81.67) ; U2.3 U2.8 v2(131.83,156.84) ; U30.18 v2(145.03,66.05) ; C19.2 122.05,144.27 121.91,144.27 v2(121.91,144.26) ; U36.34 v2(34.96,50.28) ; U27.N20 v1(88.09,84.38) U27.M20 ; C242.2 v2(113.79,27.56) ; R114.2 v2(158.24,54.1) ; v1(95.89,83.73) U27.M9 ; v1(95.89,83.73) U27.M8 ; v1(95.89,83.73) U27.L8 U27.K9 U27.J10 v1(95.24,81.78) U27.H10 ; v2(48.26,88.93) C89.2 v2(50.67,88.93) ; R64.2 v2(55.12,89.85) ; v1(91.69,92.97) 91.69,92.54 U27.AE15 ; v2(79.12,59.56) 78.87,59.31 R106.1 ; 47.62,42.8 47.37,43.05 47.37,44.2 ; U36.57 26.07,55.91 v2(26.29,56.13) 26.57,55.86 U36.56 ; R76.2 v2(55.12,75.56) ; U22.2 v2(40.64,98.55) ; RJ14.1 v2(95.38,19.43) ; U27.G8 v1(96.54,81.13) U27.H8 ; U25.12 v2(168.39,96.79) ; U27.AE1 v4(101.22,92.96) ; U25.24 v2(154.01,82.79) ; C130.2 v2(78.36,59.74) ; U11.11 v2(126.86,150.14) ; 42.46,99.82 v2(40.64,99.82) ; C104.2 v2(44.2,81.91) ; U27.H18 v1(89.39,81.78) U27.H19 ; U25.13 v2(153.94,96.79) ; C81.2 13.53,102.62 v2(13.3,102.39) ; C95.2 v2(44.2,85.47) ; U29.G8 v4(60.15,77.97)
  TOP w0.279: U32.41 87.52,55.38 v2(87.25,55.12) ; U32.20 82.93,55.38 v2(83.19,55.12)
  TOP w0.305: U27.AA9 v1(95.89,89.58) U27.AA8 ; C234.2 v2(169.1,28.19) ; U37.33 v2(137.73,53.15) ; U23.B9 v4(64.15,91.4) ; 70.99,25.91 71.25,25.65 71.25,24.26 71.88,23.62 76.2,23.62 77.09,24.51 77.09,25.53 ; 70.99,25.91 70.48,25.91 70.28,25.7 C241.2 ; 70.99,25.91 70.99,26.15 71.3,26.46 U49.4 71.93,25.48 v2(72.26,25.15) 72.9,24.51 C246.2 ; D1.2 v2(147.7,156.68) ; U27.J14 v1(91.99,81.78) U27.H14 ; U27.K11 v1(94.59,83.08) U27.L11 ; U27.M16 v1(91.34,84.38) U27.N16 ; U51.2 141.19,15.97 v5(141.22,16) ; U23.E8 v4(61.75,92.2) ; U29.B9 v4(64.15,77.17) ; U14.3 149.46,148.35 v2(149.22,148.59) ; 168.02,110.57 J6.2 ; J6.2 168.02,113.46 ; J6.2 166.57,112.01 ; J6.2 169.47,112.01 ; U37.50 v2(129.67,49.35) ; P1.17 v2(108.92,162.46) ; U12.13 155.26,144.34 v2(155.57,144.02) ; P1.8 v2(104.42,162.46) ; 70.99,33.4 70.99,33.64 71.3,33.95 U41.4 71.93,32.97 v2(72.26,32.64) 72.9,32 C218.2 ; 70.99,33.4 70.48,33.4 70.28,33.2 C208.2 ; 70.99,33.4 71.25,33.15 71.25,31.75 71.88,31.11 76.2,31.11 77.09,32 77.09,33.02 ; 162.94,110.57 162.94,112.01 ; 162.94,112.01 162.94,113.46 ; 162.94,112.01 164.39,112.01 ; 162.94,112.01 161.49,112.01 ; J14.16 v2(118.68,46.8) ; v2(63.63,36.83) 63.63,36.32 63.2,35.89 C205.2 63.04,35.89 62.64,36.3 v2(62.64,36.83) ; P1.5 v2(102.92,162.46) ; v2(152.53,57.15) 152.65,57.03 152.65,56.86 152.64,56.85 152.64,56.43 152.65,56.42 U33.6 ; J13.2 166.42,53.59 ; J13.2 164.03,53.59 ; J13.2 165.23,52.4 ; 161.54,48.08 P5.4 ; P5.4 163.12,49.66 ; P5.4 159.97,49.66 ; P5.4 161.54,51.23 ; v1(92.64,90.23) U27.AA13 ; C21.2 v2(21.08,144.59) ; U38.2 98.81,43.43 v2(98.42,43.05) ; D2.2 v2(150.62,156.68) ; U29.F9 v4(60.95,77.17) ; P5.5 163.12,44.58 ; P5.5 159.97,44.58 ; P5.5 161.54,43 ; P5.5 161.54,46.15 ; P5.2 168.2,49.66 ; P5.2 165.05,49.66 ; P5.2 166.62,48.08 ; P5.2 166.62,51.23 ; U29.G1 v4(60.15,84.37) ; U31.G7 v2(126.21,68.41) ; U31.G3 v2(121.2,68.41) ; U31.H9 v2(128.21,67.41) ; U31.H2 v2(120.2,67.41) ; C228.2 v2(165.35,26.61) ; C54.1 79.88,119.38 v2(79.76,119.25) ; U31.G9 v2(128.21,68.41) ; 161.49,106.93 162.94,106.93 ; 162.94,106.93 162.94,108.38 ; 162.94,106.93 162.94,105.49 ; 162.94,106.93 164.39,106.93 ; P1.2 v2(101.41,162.46) ; v2(77.56,49.91) 77.56,48.59 C165.2 ; U27.L13 v1(92.64,83.08) U27.K13 ; R32.2 v2(110.74,152.02) ; C48.1 73.79,122.55 v2(73.66,122.68) ; C166.2 91.61,49.9 v2(91.62,49.91) ; C166.2 90.66,48.59 90.53,48.72 v2(90.53,49.89) ; C166.2 92.35,48.59 92.66,48.89 v2(92.66,49.94) ; R115.2 v2(93.27,53.21) ; v2(83.57,130.05) 83.06,130.05 82.63,129.62 C29.2 82.63,129.46 83.06,129.03 v2(83.57,129.03) ; U27.J17 v1(90.04,82.43) U27.K17 ; U29.P1 v4(53.75,84.37) ; U29.B3 v4(64.15,82.77) ; U27.Y7 v1(97.19,89.58) U27.AA7 ; U27.M14 92.64,84.38 U27.N14 92.31,84.71 v1(92.64,85.03) 92.96,85.36 U27.P13 v1(93.29,85.68) U27.R13 ; U23.G1 v4(60.15,98.6) ; U12.4 v2(155.26,149.42) ; U23.B1 v4(64.15,98.6) ; R13.2 163.63,144.14 v2(163.16,144.61) Q2.4 ; U24.14 123.56,95.49 v2(123.7,95.63) 123.33,95.99 U24.15 ; U27.R11 v1(94.59,85.68) U27.P11 ; v2(127.13,37.02) 127.38,36.77 127.38,35.56 ; U29.T9 v4(52.15,77.17) ; U75.3 115.43,91.96 v2(115.95,91.44) 116.33,91.44 116.73,91.84 U75.1 ; U38.3 v2(98.42,42.16) ; C24.2 v2(19.24,142.24) ; v2(79.36,49.91) 79.36,48.84 79.11,48.59 C165.2 ; U23.G9 v4(60.15,91.4) ; U29.T1 v4(52.15,84.37) ; U44.12 156.03,36 v5(156.34,35.69) ; 54.61,108.84 54.58,108.86 54.58,110.21 54.8,110.43 54.8,111.7 54.58,111.91 U19.10 54.58,115.93 v2(54.74,116.08) ; U29.D1 v4(62.55,84.37) ; U29.D8 v4(62.55,77.97) ; v2(83.57,123.82) 82.67,124.72 U18.9 80.39,124.72 80.14,124.97 v2(79.38,124.97) ; C22.2 v2(22.86,144.59) ; U33.44 156.86,52.82 v2(156.97,52.7) ; U19.13 56.54,112.88 v2(56.9,112.52) ; v4(84.84,92.96) 85.16,92.64 U27.AE25 ; U24.9 v2(121.78,91.83) ; C171.2 v2(154.94,44.07) ; R112.2 v2(93.17,54.36) ; J6.3 169.47,106.93 ; J6.3 168.02,108.38 ; J6.3 168.02,105.49 ; J6.3 166.57,106.93 ; U45.2 v2(135,37.02) ; U18.3 79.13,119.25 ; C116.2 v2(140.84,74.99) ; U27.P17 v1(90.04,85.03) U27.N17 ; U23.T9 v4(52.15,91.4) ; U31.L8 v2(127.21,63.41) ; 77.09,25.53 v2(77.57,25.53) 77.57,26.06 77.17,26.47 C237.2 77.01,26.47 76.58,26.03 v2(76.58,25.53) 77.09,25.53 ; U29.P9 v4(53.75,77.17) ; v2(63.63,29.34) 63.63,28.83 63.2,28.4 C235.2 63.04,28.4 62.64,28.8 v2(62.64,29.34) ; J14.64 v2(108.71,51.31) J14.63 v2(114.94,51.31) J14.62 v2(121.16,51.31) J14.61 ; C165.2 v2(78.52,49.91) ; P5.3 166.62,46.15 ; P5.3 165.05,44.58 ; P5.3 168.2,44.58 ; P5.3 166.62,43 ; C173.2 v2(150.47,43.87) ; C131.2 v2(140.84,58.04) ; U23.T1 v4(52.15,98.6) ; R110.1 v2(159.89,54.86) ; U23.D1 v4(62.55,98.6) ; Q1.4 v2(149.01,152.15) ; v2(116.2,31.36) 116.2,31.93 C212.2 116.97,31.93 v2(116.97,31.36) ; R11.2 v2(128.27,141.6) ; R146.1 v3(145.03,26.92) ; U23.M1 v4(55.35,98.6) ; U23.E1 v4(61.75,98.6) ; U23.G8 v4(60.15,92.2) ; v2(147.07,126.36) 147.57,125.86 C543.2 ; C134.1 v2(154.31,60.71) ; U23.F9 v4(60.95,91.4) ; P1.11 v2(105.92,162.46) ; C18.2 v2(119.38,144.78) ; J14.57 v2(108.19,55.86) ; R161.1 v3(142.49,24.13) ; v2(52.96,117.86) 52.63,118.18 U19.22 ; 77.09,33.02 v2(76.58,33.02) 76.58,33.53 77.01,33.96 C207.2 77.17,33.96 77.57,33.55 v2(77.57,33.02) 77.09,33.02 ; RJ1.3 v2(129.41,148.59) ; U24.8 v2(120.28,91.83) ; Q2.1 v2(161.15,141.87) ; U29.G9 v4(60.15,77.17) ; U43.2 146.33,35.68 146.3,35.65 v5(146.3,35.05) U43.15 ; U29.B1 v4(64.15,84.37) ; C110.2 v2(43.89,78.69) ; R6.2 v2(119.38,145.92) ; U31.G5 v2(123.21,68.41) ; U37.21 v2(141.07,44.35) ; U31.P2 v2(120.2,60.41) ; U29.E2 v4(61.75,83.57) ; U27.P15 v1(91.99,85.68) U27.R15 ; C127.2 v2(148.97,64.9) ; v2(55.75,101.85) 56.32,101.28 C82.2 ; U31.M4 v2(122.2,62.41) ; U13.3 146.42,148.35 v2(146.18,148.59) ; C190.2 v2(110.11,40.53) ; U37.61 v2(129.64,43.85) ; U27.L18 v1(89.39,83.73) U27.M18 ; U27.P9 v1(95.89,85.68) U27.R9 ; U23.B3 v4(64.15,97) ; v2(68.22,82.52) C96.2 v2(66.93,82.52) ; v2(129.04,39.37) 128.47,39.37 C189.2 128.47,38.61 v2(129.04,38.61) ; C133.2 v2(152.27,60.71) ; C167.2 157.1,44.32 v2(156.97,44.2) ; R4.2 v2(119.38,148.21) ; U29.M9 v4(55.35,77.17) ; R5.2 v2(119.38,147.07) ; U27.AB8 v1(96.54,90.23) ; C8.2 v2(11.75,152.27) ; U47.5 v2(109.73,27.5) ; C63.1 v2(61.47,116.08) ; U38.4 v2(98.42,40.89) ; v2(48.89,95.45) C84.2 v2(50.39,95.43) ; J14.58 v2(108.19,46.75) ; U27.AA15 v1(91.99,89.58) U27.Y14 ; U31.L3 v2(121.2,63.41) ; DS1.1 v2(10.9,150.22) ; U31.M7 v2(125.22,63.4) ; U31.G6 v2(125.21,68.41) ; U26.1 v2(149.59,88) ; U37.12 v2(135.73,38.96) ; Y2.4 115.77,40.08 115.95,40.26 v2(115.96,40.26) ; U29.J2 v4(57.75,83.57) ; C123.2 v2(150.62,68.96) ; U31.G8 v2(127.21,68.41) ; U29.E1 v4(61.75,84.37) ; U29.A9 v4(64.95,77.17) ; U27.R8 v1(95.89,86.33) U27.T8 ; U29.M1 v4(55.35,84.37) ; C122.2 v2(149.22,71.12) ; C172.1 v2(153.67,43.43) ; U19.14 v2(57.91,114.05) ; U27.K15 v1(91.34,83.08) U27.L15 ; Q1.1 v2(150.96,149.44) ; U29.J8 v4(57.75,77.97) ; U23.D8 v4(62.55,92.2) ; R147.1 v3(146.3,26.92) ; D15.3 v2(50.93,26.67) ; U31.G4 v2(122.2,68.41) ; C132.2 v2(142.75,58.04) ; 73.15,62.23 v2(73.91,62.23) ; R409.2 v2(161.04,125.98) ; Q8.1 v2(86.6,41.16) ; U23.E2 v4(61.75,97.8) ; U23.J8 v4(57.75,92.2) ; U31.J5 v2(123.21,66.41) ; R160.1 v3(141.22,24.13) ; U23.M9 v4(55.35,91.4) ; U29.E8 v4(61.75,77.97) ; C129.2 v2(148.97,63.37) ; C256.2 v2(151.13,15.62) ; C135.1 v2(157.23,60.58) ; U31.G2 v2(120.2,68.41) ; U23.P1 v4(53.75,98.6) ; U23.J2 v4(57.75,97.8) ; Y2.2 v2(113.59,41.99) ; U23.A9 v4(64.95,91.4) ; U23.P9 v4(53.75,91.4) ; C128.2 v2(151.13,65.66) ; C142.2 v2(155.7,60.07) ; U31.P9 v2(128.21,60.41)
  TOP w0.381: v2(76.83,62.23) 76.83,63.27 77.22,63.65 C126.2 78.61,63.65 78.99,63.27 v2(78.99,62.23) ; v2(77.03,57.78) C130.2 77.03,60.58 77.41,60.96 v2(78.36,60.96) ; v4(81.78,76.15) C108.2 80.44,75.95 v4(79.57,75.95)
  TOP w0.406: R78.2 v2(41.02,76.58) ; U28.39 v2(25.08,86.93) ; U28.49 v2(25.08,80.58) ; RJ7.1 v2(36.07,89.53) ; v2(31.24,93.34) 31.31,93.28 U28.28 ; U28.52 24.96,78.68 v2(25.27,78.36) ; v2(31.37,86.36) 31.43,86.3 U28.17 ; U28.36 v2(25.08,88.84) ; U28.33 v2(25.08,90.74) ; RJ10.1 v2(36.07,86.99) ; C117.1 v2(35.56,74.42) ; U28.46 v2(25.08,82.49) ; RJ6.1 v2(36.07,90.8) ; U28.1 v2(32.86,75.21)
  TOP w0.508: 155.75,64.43 P2.SH3 ; P2.SH3 157.39,65.71 ; P2.SH3 157.39,63.14 ; 50.42,34.81 50.42,35.56 ; 50.42,35.56 51.17,35.56 ; 50.42,35.56 50.42,36.31 ; J20.3 88.65,156.45 ; J20.3 89.78,155.32 ; J20.3 87.52,155.32 ; J20.3 88.65,154.19 ; P4.1 v2(4.95,46.61) ; 39.64,36.07 40.39,36.07 40.39,35.32 ; J16.3 43.69,19.1 ; J16.3 42.11,17.53 ; J16.3 45.26,17.53 ; J16.3 43.69,15.95 ; C168.1 v2(49.78,45.08) ; 59.31,47.38 C164.1 ; C164.1 v2(58.55,48.13) ; C164.1 59.31,48.88 ; J18.4 29.97,19.99 ; J18.4 31.55,18.41 ; J18.4 28.4,18.41 ; J18.4 29.97,16.84 ; 161.52,69.43 P2.SH1 ; P2.SH1 163.16,68.15 ; P2.SH1 163.16,70.71 ; P2.SH1 164.8,69.43 ; C222.2 v2(90.68,30.23) ; P2.SH4 163.16,65.71 ; P2.SH4 163.16,63.14 ; P2.SH4 164.8,64.43 ; P2.SH4 161.52,64.43 ; P1.MTG1 112.9,163.29 ; P1.MTG1 112.9,160.52 ; P1.MTG1 114.29,161.91 ; P1.MTG1 111.52,161.91 ; v2(146.43,41.66) 146,41.66 C181.2 146,40.64 v2(146.43,40.64) ; v2(67.13,58.17) 66.75,58.17 C143.1 66.75,59.18 v2(67.13,59.18) ; v2(66.93,50.67) 66.93,50.16 66.42,49.66 ; 34.05,20.95 C252.2 ; C252.2 35.05,20.08 ; C252.2 36.06,20.95 ; C254.2 33.27,21.7 ; C254.2 33.27,20.21 ; C254.2 34.02,20.95 ; 147.74,160.81 J2.G2 ; J2.G2 146.03,162.52 ; J2.G2 147.74,164.22 ; J2.G2 149.44,162.52 ; v2(65.97,53.97) 65.29,53.97 C157.1 ; v2(57.84,54.61) 58.34,54.61 C156.1 58.34,53.59 v2(57.84,53.59) ; R126.2 54.1,49.01 ; R126.2 54.85,48.26 ; R126.2 54.1,47.51 ; C188.2 v2(70.87,39.37) ; 31.13,164.59 C1.2 ; C1.2 32.38,163.33 ; C1.2 33.64,164.59 ; C1.2 32.38,165.85 ; C224.2 32.37,29.59 ; C224.2 31.62,30.34 ; C224.2 31.62,28.84 ; v2(159.64,150.62) 159.64,150.11 C12.2 158.62,150.11 v2(158.62,150.62) ; 112.13,166.81 P1.MTG3 ; P1.MTG3 113.51,165.42 ; P1.MTG3 114.9,166.81 ; P1.MTG3 113.51,168.19 ; C2.2 51.42,164.59 ; C2.2 48.91,164.59 ; C2.2 50.16,165.85 ; C2.2 50.16,163.33 ; 32.03,22.48 D18.3 31.04,21.69 ; v2(17.91,100.84) 17.65,100.58 17.65,100.08 ; C3.2 69.2,164.59 ; C3.2 67.94,163.33 ; C3.2 67.94,165.85 ; C3.2 66.69,164.59 ; 54.85,25.15 C243.2 53.85,24.27 ; R118.1 C160.1 v2(67.69,51.18) ; TP16.1 v2(21.46,105.79) ; 35.69,25.67 R155.2 36.44,26.42 ; 42.24,26.49 D14.2 ; D14.2 42.24,27.86 ; D14.2 41.26,27.18 ; D14.2 43.22,27.18 ; 22.73,39.89 C186.1 ; C186.1 22.73,41.39 ; C186.1 21.98,40.64 ; 159.17,162.52 J2.G1 ; J2.G1 160.87,160.81 ; J2.G1 162.58,162.52 ; J2.G1 160.87,164.22 ; C73.2 v2(16.26,108.97) ; C6.1 v2(159.77,153.42) ; C71.2 v2(11.68,108.97) ; v2(119.51,139.95) 120.02,139.95 C25.2 120.02,140.97 v2(119.51,140.97) ; v2(100.33,156.21) U4.2 ; C161.1 v2(58.04,50.16) ; C161.1 C158.1 ; C161.1 57.29,50.93 ; 20.84,31.88 C213.2 21.59,31.13 ; C72.2 v2(13.97,108.97) ; 23.32,18.41 J18.5 ; J18.5 24.89,16.84 ; J18.5 24.89,19.99 ; J18.5 26.47,18.41 ; R52.2 v2(15.11,108.97) ; 48.77,21.03 J16.4 ; J16.4 48.77,24.18 ; J16.4 50.34,22.61 ; J16.4 47.19,22.61 ; U3.2 v2(97.79,156.15) ; v2(150.95,41.02) 151.38,41.02 C177.2 151.38,42.04 v2(150.95,42.04) ; 80.77,158.25 J3.2 ; J3.2 80.77,160.52 ; J3.2 79.64,159.38 ; J3.2 81.9,159.38 ; 161.27,64.8 P2.4 162.41,65.93 ; C155.1 v2(65.91,55.12) ; 131.7,158.22 J1.7 ; J1.7 130.9,159.02 ; J1.7 131.7,159.82 ; J1.7 132.5,159.02 ; v2(118.49,155.07) 119,155.07 C5.2 119,154.05 v2(118.49,154.05) ; J18.2 29.97,14.91 ; J18.2 28.4,13.33 ; J18.2 31.55,13.33 ; J18.2 29.97,11.76 ; 8.25,124.85 J4.4 ; J4.4 6.62,126.49 ; J4.4 9.89,126.49 ; J4.4 8.25,128.13 ; TP60.1 v2(65.66,20.7) ; 54.48,29.86 R144.2 55.23,30.61 ; v2(102.3,154.31) U8.2 ; 66.42,49.66 65.91,50.16 v2(65.91,50.67) ; 66.42,49.66 C163.1 ; v2(19.94,99.69) 19.43,100.2 C83.2 ; D17.2 23.44,23.67 ; D17.2 23.44,22.3 ; D17.2 24.42,22.99 ; D17.2 22.47,22.99 ; 22.86,37.96 C195.2 22.11,37.21 ; C219.2 31.62,32.12 ; C219.2 31.62,30.62 ; C219.2 32.37,31.37 ; J1.G1 138.27,164.22 ; J1.G1 136.57,162.52 ; J1.G1 139.97,162.52 ; J1.G1 138.27,160.81 ; J18.3 26.47,13.33 ; J18.3 23.32,13.33 ; J18.3 24.89,14.91 ; J18.3 24.89,11.76 ; v2(67.13,56.13) 66.75,56.13 C153.1 66.75,57.15 v2(67.13,57.15) ; P1.MTG2 98.42,163.29 ; P1.MTG2 98.42,160.52 ; P1.MTG2 97.04,161.91 ; P1.MTG2 99.81,161.91 ; 6.62,131.57 J4.3 ; J4.3 9.89,131.57 ; J4.3 8.25,133.21 ; J4.3 8.25,129.93 ; J16.5 43.69,24.18 ; J16.5 42.11,22.61 ; J16.5 43.69,21.03 ; J16.5 45.26,22.61 ; J2.4 150.8,161.32 ; J2.4 151.61,160.52 ; J2.4 150,160.52 ; U7.2 v2(100.81,154.28) ; J16.2 50.34,17.53 ; J16.2 47.19,17.53 ; J16.2 48.77,19.1 ; J16.2 48.77,15.95 ; C78.2 v2(17.86,105.46) ; v2(164.08,24.59) 164.08,25.02 C239.2 163.07,25.02 v2(163.07,24.59) ; v2(119.51,143.51) 120.02,143.51 C20.2 120.02,142.49 v2(119.51,142.49) ; C119.2 v2(110.87,70.36) ; 41.66,42.15 C182.2 40.91,41.4 ; J1.G2 126.83,162.52 ; 96.43,166.81 P1.MTG4 ; P1.MTG4 97.82,168.19 ; P1.MTG4 97.82,165.42 ; P1.MTG4 99.2,166.81 ; P7.1 v2(4.95,23.75) ; v2(57.84,58.93) 58.34,58.93 C144.1 58.34,57.91 v2(57.84,57.91) ; P8.1 v2(4.95,12.32) ; v2(106.4,154.25) U10.2 ; 50.42,33.03 50.42,33.78 ; 50.42,33.78 51.17,33.78 ; 50.42,33.78 50.42,34.53 ; U9.2 v2(104.9,154.24) ; v2(166.88,20.9) 166.88,21.34 C249.2 167.89,21.34 v2(167.89,20.9) ; v2(106.93,156.21) U5.2 ; P3.1 v2(4.95,58.04) ; 52.2,24.4 C244.2 ; v2(166.12,60.5) 166.12,60.07 C146.2 167.13,60.07 v2(167.13,60.5) ; C114.2 v2(106.43,73.79) ; J2.7 154.31,159.82 ; P6.1 v2(4.95,35.18) ; C60.2 v2(100.71,115.06) ; C118.2 v2(109.35,71.29) ; v2(118.49,152.65) 119,152.65 C9.2 119,151.64 v2(118.49,151.64) ; TP17.1 v2(127.38,109.73) ; J7.5 v2(9.65,102.29) ; C120.2 v2(112.9,70.36) ; v2(57.84,55.75) 58.34,55.75 C154.1 58.34,56.77 v2(57.84,56.77) ; TP39.1 v2(137.16,58.93) ; v2(163.32,55.58) 163.32,56.01 C145.2 162.31,56.01 v2(162.31,55.58) ; C4.1 v2(119.63,156.46) ; v2(109.41,156.21) U6.2 ; 157.39,68.15 P2.SH2 ; 30.23,40.89 v2(30.99,40.89)
  TOP w0.635: 4.87,161.16 J22.2 ; J22.2 7.13,161.16 ; J22.2 6,159.38 ; J22.2 6,162.94 ; J22.MTG2 6.89,165.66 ; J22.MTG2 5,164.53 ; J22.MTG2 5,166.79 ; J22.MTG2 3.11,165.66 ; J22.MTG1 5,157.79 ; J22.MTG1 6.89,156.66 ; J22.MTG1 5,155.53 ; J22.MTG1 3.11,156.66
  L2_GND w0.508: 165.18,44.58 P5.3 ; P5.3 166.62,43.13 ; P5.3 166.62,46.03 ; P5.3 168.07,44.58 ; 125.13,160.8 J1.G2 ; J1.G2 126.84,162.52 ; J1.G2 123.41,162.52 ; J1.G2 125.13,164.23 ; 157.39,62.96 P2.SH3 ; P2.SH3 156.25,64.43 ; P2.SH3 159.29,64.43 ; P2.SH3 157.39,65.9 ; J2.G1 160.87,164.23 ; J2.G1 160.87,160.8 ; J2.G1 159.16,162.52 ; J2.G1 162.59,162.52 ; J18.3 26.34,13.33 ; J18.3 24.89,14.78 ; J18.3 24.89,11.89 ; J18.3 23.44,13.33 ; 147.74,160.8 J2.G2 ; J2.G2 146.02,162.52 ; J2.G2 149.45,162.52 ; J2.G2 147.74,164.23 ; P2.SH1 163.16,70.9 ; P2.SH1 163.16,67.96 ; P2.SH1 164.3,69.43 ; P2.SH1 161.26,69.43 ; P5.2 168.07,49.66 ; P5.2 166.62,48.21 ; P5.2 166.62,51.11 ; P5.2 165.18,49.66 ; J1.7 132.51,159.02 ; J1.7 131.7,158.2 ; J1.7 130.89,159.02 ; J1.7 131.7,159.83 ; J15.2 105.92,38.28 ; J15.2 104.85,37.21 ; J15.2 106.99,37.21 ; J15.2 105.92,36.14 ; C2.2 51.44,164.59 ; C2.2 50.16,163.32 ; C2.2 50.16,165.86 ; C2.2 48.89,164.59 ; 105.92,20.9 J15.14 ; J15.14 104.85,21.97 ; J15.14 105.92,23.04 ; J15.14 106.99,21.97 ; J18.2 31.42,13.33 ; J18.2 29.97,14.78 ; J18.2 28.52,13.33 ; J18.2 29.97,11.89 ; J13.2 166.29,53.59 ; J13.2 164.16,53.59 ; J13.2 165.23,54.66 ; J13.2 165.23,52.53 ; J1.4 128.2,161.33 ; J1.4 129.01,160.52 ; J1.4 127.39,160.52 ; J16.4 48.77,24.05 ; J16.4 48.77,21.16 ; J16.4 47.32,22.61 ; J16.4 50.22,22.61 ; 162.94,112.01 162.94,113.46 ; 162.94,112.01 162.94,110.57 ; 162.94,112.01 161.49,112.01 ; 162.94,112.01 164.39,112.01 ; 146.35,57.99 J10.2 ; J10.2 146.35,60.12 ; J10.2 145.29,59.05 ; J16.5 45.14,22.61 ; J16.5 43.69,24.05 ; J16.5 43.69,21.16 ; J16.5 42.24,22.61 ; 80.77,158.32 J3.2 ; J3.2 79.7,159.38 ; J3.2 81.84,159.38 ; J3.2 80.77,160.45 ; J15.12 105.92,25.58 ; J15.12 105.92,23.44 ; J15.12 104.85,24.51 ; J15.12 106.99,24.51 ; 43.69,16.08 J16.3 ; J16.3 43.69,18.97 ; J16.3 42.24,17.53 ; J16.3 45.14,17.53 ; 88.65,154.25 J20.3 ; J20.3 88.65,156.39 ; J20.3 87.58,155.32 ; J20.3 89.71,155.32 ; P1.MTG4 97.82,168.13 ; P1.MTG4 99.14,166.81 ; P1.MTG4 96.49,166.81 ; P1.MTG4 97.82,165.49 ; J4.3 8.25,133.15 ; J4.3 8.25,130 ; J4.3 6.68,131.57 ; J4.3 9.83,131.57 ; 162.94,106.93 164.39,106.93 ; 162.94,106.93 162.94,108.38 ; 162.94,106.93 161.49,106.93 ; 162.94,106.93 162.94,105.49 ; J1.G1 138.27,164.23 ; J1.G1 138.27,160.8 ; J1.G1 139.98,162.52 ; J1.G1 136.55,162.52 ; 166.57,106.93 J6.3 ; J6.3 168.02,105.49 ; J6.3 168.02,108.38 ; 28.52,18.41 J18.4 ; J18.4 29.97,16.97 ; J18.4 29.97,19.86 ; J18.4 31.42,18.41 ; J18.5 24.89,19.86 ; J18.5 26.34,18.41 ; J18.5 24.89,16.97 ; J18.5 23.44,18.41 ; J2.7 154.31,159.83 ; J2.7 154.31,158.2 ; J2.7 155.12,159.02 ; J2.7 153.49,159.02 ; 168.02,110.57 J6.2 ; J6.2 168.02,113.46 ; J6.2 166.57,112.01 ; C23.2 74.68,146.81 ; C23.2 73.41,148.08 ; C23.2 72.14,146.81 ; C23.2 73.41,145.54 ; 6.68,126.49 J4.4 ; J4.4 8.25,128.07 ; J4.4 8.25,124.92 ; J4.4 9.83,126.49 ; 66.67,164.59 C3.2 ; C3.2 69.22,164.59 ; C3.2 67.94,163.32 ; C3.2 67.94,165.86 ; 160.1,49.66 P5.4 ; P5.4 161.54,51.11 ; P5.4 162.99,49.66 ; P5.4 161.54,48.21 ; 32.38,163.32 C1.2 ; C1.2 32.38,165.86 ; C1.2 31.11,164.59 ; C1.2 33.66,164.59 ; 160.1,44.58 P5.5 ; P5.5 161.54,46.03 ; P5.5 162.99,44.58 ; P5.5 161.54,43.13 ; 111.58,161.91 P1.MTG1 ; P1.MTG1 112.9,160.59 ; P1.MTG1 112.9,163.23 ; P1.MTG1 114.22,161.91 ; C65.2 28.7,113.41 ; C65.2 28.7,110.87 ; C65.2 27.43,112.14 ; C65.2 29.97,112.14 ; J2.4 151.62,160.52 ; J2.4 149.99,160.52 ; J2.4 150.8,161.33 ; P1.MTG2 98.42,163.23 ; P1.MTG2 98.42,160.59 ; P1.MTG2 97.1,161.91 ; P1.MTG2 99.75,161.91 ; P1.MTG3 113.51,168.13 ; P1.MTG3 113.51,165.49 ; P1.MTG3 112.19,166.81 ; P1.MTG3 114.83,166.81 ; J16.2 48.77,18.97 ; J16.2 48.77,16.08 ; J16.2 50.22,17.53 ; J16.2 47.32,17.53 ; P2.SH2 157.39,70.9 ; P2.SH2 157.39,67.96 ; P2.SH2 156.25,69.43 ; P2.SH2 159.29,69.43 ; 118.72,20.24 J17.5 ; 161.27,64.86 P2.4 162.34,65.93 ; P2.SH4 163.16,65.9 ; P2.SH4 164.3,64.43 ; P2.SH4 163.16,62.96 ; P2.SH4 161.26,64.43 ; 120.73,20.24 J17.6
  L2_GND w0.635: 5,155.52 J22.MTG1 ; J22.MTG1 5,157.81 ; J22.MTG1 6.91,156.66 ; J22.MTG1 3.09,156.66 ; J22.MTG2 5,166.81 ; J22.MTG2 3.09,165.66 ; J22.MTG2 5,164.52 ; J22.MTG2 6.91,165.66 ; J22.2 6,162.95 ; J22.2 4.86,161.16 ; J22.2 6,159.37 ; J22.2 7.14,161.16
  LY3 w0.305: 97.1,161.91 P1.MTG2 ; P1.MTG2 98.42,160.59 ; P1.MTG2 98.42,163.23 ; P1.MTG2 99.75,161.91 ; J1.G1 138.27,164.23 ; J1.G1 139.98,162.52 ; J1.G1 138.27,160.8 ; J1.G1 136.55,162.52 ; 123.41,162.52 J1.G2 ; J1.G2 125.13,164.23 ; J1.G2 126.84,162.52 ; J1.G2 125.13,160.8 ; 97.82,165.49 P1.MTG4 ; P1.MTG4 99.14,166.81 ; P1.MTG4 96.49,166.81 ; P1.MTG4 97.82,168.13 ; P1.MTG1 112.9,163.23 ; P1.MTG1 112.9,160.59 ; P1.MTG1 111.58,161.91 ; P1.MTG1 114.22,161.91 ; 113.51,165.49 P1.MTG3 ; P1.MTG3 112.19,166.81 ; P1.MTG3 113.51,168.13 ; P1.MTG3 114.83,166.81 ; J1.7 132.51,159.02 ; J1.7 130.89,159.02 ; J1.7 131.7,158.2 ; J1.7 131.7,159.83 ; J1.4 128.2,161.33 ; J1.4 127.39,160.52 ; J1.4 129.01,160.52
  LY4 w0.305: v2(53.59,129.03) 53.59,129.92 53.92,130.25 54.28,130.25 54.99,129.54 54.99,127.25 60.2,122.05 63.5,122.05 64.26,121.28 64.26,120.4 63.75,119.89 62.86,119.89 v2(62.61,120.14)
  BOTTOM w0.254: v1(90.69,87.63) C319.2 ; v4(75.13,89.99) C312.2 v4(75.13,88.65) ; U63.2 10.05,26.02 C529.1 9.02,26.03 C528.2 v2(8,26.29) ; v2(129.67,49.35) 129.36,49.66 C482.1 ; v2(21.08,59.26) U56.1 ; v4(76.91,89.99) C311.2 v4(76.91,88.65) ; R369.2 153.29,36.19 v5(153.8,35.69) ; C493.2 v2(144.53,45.59) 144.53,44.7 ; U55.4 v2(41.4,61.85) ; v4(79.63,94.62) C295.2 79.59,93.88 79.22,93.88 v4(78.98,93.64) ; v4(81.78,92.71) C297.2 v4(82.42,93.36) ; v2(159.56,31.57) 159.56,31.29 R381.2 R384.2 ; C308.2 v1(91.99,89.58) ; v5(155.07,35.69) 155.45,36.07 R368.2 ; C481.2 88.2,49.7 v2(88.23,49.68) ; R261.2 38.86,82.3 v2(40.13,82.3) ; U52.24 18.52,105.17 v2(18.76,105.41) ; U65.2 10.05,14.59 C534.1 9.02,14.6 C533.2 v2(8,14.86) ; C305.2 v4(60.15,91.4) ; C336.2 v4(64.15,84.37) ; J21.40 v2(147.17,93.22) ; v1(91.34,84.38) C341.2 ; v4(81.92,87) 82.16,87.24 C322.2 ; C495.2 28.19,46.61 v2(28.07,46.74) ; C526.2 v2(121.67,25.72) ; U52.20 16.51,105.17 v2(16.88,105.54) ; v2(140.59,67.59) 140.84,67.84 C409.2 ; R367.2 R362.2 v2(158.75,38.73) ; 91.14,71.23 91.14,71.23 v4(91.13,71.22) ; C318.2 v1(95.89,88.28) ; v2(8,37.72) C510.2 9.02,37.46 C512.1 10.05,37.45 U61.2 ; R298.2 140.34,64.74 v2(140.59,65) ; C279.2 v4(61.75,98.6) ; C383.2 v4(60.15,77.17) ; v2(81.28,86.94) 81.28,86.7 81.63,86.35 C331.2 ; U52.17 15.01,105.13 v2(14.86,105.28) ; C375.1 72.52,78.36 72.43,78.44 v2(72.39,78.44) ; J21.16 v2(135.16,93.25) ; v5(154.43,50.04) 154.94,49.53 C486.2 ; R379.2 156.97,32.51 v5(156.34,33.15) ; R333.1 v2(21.21,47.24) ; C298.2 89.46,92.97 v1(91.69,92.97) ; v2(86.6,41.16) 86.61,41.15 R373.1 ; 96.8,71.13 96.8,71.36 C403.2 ; C337.2 v4(61.75,84.37) ; v2(139.45,93.22) 139.66,93.43 J21.25 ; U74.2 v2(33.9,141.34) ; v4(80.39,94.11) 80.7,94.11 81.02,94.43 C294.2 81.03,94.44 81.41,94.82 v4(81.41,94.99) ; v2(117.57,153.13) 117.17,153.54 C268.2 C269.2 ; v1(91.99,81.78) 92.33,82.42 ; v1(92.64,86.98) C321.2 ; C300.2 v4(64.95,91.4) ; U52.26 v2(20.3,103.23) ; U74.1 33.77,141.84 v2(33.91,141.99) ; C483.2 v2(42.99,49.66) ; 28.57,61.86 v2(29.97,61.86) ; C309.2 v1(92.64,90.23) ; C280.2 v4(55.35,98.6) ; v1(90.04,85.03) 90.04,85.03 C349.2 ; C304.2 v4(64.15,91.4) ; 28.57,59.91 v2(30.1,59.91) 30.48,59.53 C456.1 ; v4(103.96,74.24) 104.72,74.24 C390.2 ; v1(92.64,83.08) 92.91,83.08 C347.2 ; U52.4 v2(17.01,98.56) ; R223.1 149.86,118.49 v2(150.24,118.11) ; C388.2 v4(96.82,73.66) ; v2(148.97,118.11) 148.59,118.49 R224.1 ; v2(8,49.15) C484.2 9.02,48.89 C489.1 10.05,48.88 U59.2 ; v4(82.02,94.72) 82.5,95.2 82.52,95.2 82.82,95.5 v4(83.19,95.5) ; U55.1 v2(41.45,59.9) ; C382.2 v4(64.15,77.17) ; C496.2 v2(138.43,44.83) ; C278.2 v4(64.15,98.6) ; R355.2 136.78,41.59 v2(136.91,41.72) ; 48.89,62.5 v2(50.28,62.5) ; C332.2 v1(93.29,85.68) ; U57.2 10.05,60.31 C448.1 9.02,60.32 C445.2 v2(8,60.58) ; J21.7 v2(130.66,93.24) ; R332.2 v2(138.43,46.86) ; U74.7 v2(29.33,140.34) ; R199.1 v2(152.53,149.48) ; U55.7 v2(41.45,63.8) ; C446.1 50.89,60.58 50.75,60.45 50.52,60.45 50.42,60.55 v2(50.42,60.55) 48.89,60.55 ; U73.2 v2(94.23,160.15) ; C455.1 v2(48.13,59.18) ; C340.2 v1(93.94,84.38) ; C525.2 v2(129.6,26.54) ; C271.2 v2(131.57,110.87) ; C457.1 v2(27.81,58.55) ; U56.4 v2(21.08,61.21) ; C443.2 v2(85.47,63.02) ; U56.7 v2(21.08,63.16) ; v2(144.17,93.22) J21.34 ; 153.54,44.96 v2(152.72,44.96) ; C338.2 v4(55.35,84.37) ; C378.2 v4(64.95,77.17)
  BOTTOM w0.305: U68.4 v2(145.8,132.34) ; 24.89,11.84 J18.3 ; J18.3 24.89,14.83 ; J18.3 26.39,13.33 ; J18.3 23.39,13.33 ; C463.2 88.3,57.56 ; C463.2 88.3,55.81 ; C463.2 87.8,56.69 v2(87.25,56.13) ; 28.47,13.33 J18.2 ; J18.2 29.97,11.84 ; J18.2 31.47,13.33 ; J18.2 29.97,14.83 ; R222.1 v2(79.76,119.25) ; v2(128.21,60.41) 128.52,60.09 C427.2 ; v5(151.38,50.04) 151.76,49.66 C488.2 ; C437.2 128.55,68.07 v2(128.21,68.41) ; J19.81 v2(90.29,11.51) ; C468.1 v2(148.84,56.39) ; 165.23,52.48 J13.2 ; J13.2 166.35,53.59 ; J13.2 165.23,54.71 ; J13.2 164.11,53.59 ; 162.94,112.01 162.94,113.46 ; 162.94,112.01 161.49,112.01 ; 162.94,112.01 164.39,112.01 ; 162.94,112.01 162.94,110.57 ; v2(55.75,101.85) C274.2 v2(55.75,100.08) ; 166.62,48.16 P5.2 ; P5.2 166.62,51.16 ; P5.2 168.12,49.66 ; P5.2 165.12,49.66 ; J19.69 v2(97.48,11.51) ; v2(76.58,33.02) 75.82,33.78 C517.2 ; 160.04,44.58 P5.5 ; P5.5 163.04,44.58 ; P5.5 161.54,43.08 ; P5.5 161.54,46.08 ; v1(91.34,81.13) 91.3,81.1 C368.2 ; C471.2 154.81,53.47 v5(154.43,53.09) ; R382.2 v2(137.1,30.35) ; C450.2 88.61,59.93 v2(89.1,60.43) ; C450.2 88.61,58.11 ; C450.2 87.86,59.18 ; J19.98 v2(80.09,11.51) ; P9.24 156.73,86.63 v2(156.59,86.49) ; J16.2 48.77,19.03 ; J16.2 50.27,17.53 ; J16.2 48.77,16.03 ; J16.2 47.27,17.53 ; 79.25,51.07 C477.2 ; C477.2 79.25,52.82 ; C477.2 78.5,51.94 ; R255.2 133.1,81.41 v2(132.84,81.66) ; v2(62.1,85.85) C327.2 v2(62.1,87.63) ; 87.39,62.99 C444.2 ; C444.2 88.27,63.74 ; C444.2 89.14,62.99 ; v2(100.97,19.43) 101.08,19.32 J19.58 ; 29.97,16.92 J18.4 ; J18.4 28.47,18.41 ; J18.4 29.97,19.91 ; J18.4 31.47,18.41 ; J16.3 45.19,17.53 ; J16.3 43.69,19.03 ; J16.3 43.69,16.03 ; J16.3 42.19,17.53 ; v2(64.23,89.74) C313.2 v2(64.29,88.32) ; v2(129.54,29.34) R383.2 ; 79.51,61.21 R303.2 ; R303.2 80.76,61.21 ; R303.2 80.14,61.84 ; C550.2 v2(115.95,91.44) ; J19.115 v2(69.89,11.3) ; C259.2 v2(88.27,164.59) ; R321.2 13.65,50.16 v2(13.4,50.42) R318.1 ; C436.2 v2(119.63,71.5) ; v2(76.58,25.53) 75.82,26.29 C527.2 ; R275.2 v2(144.14,72.64) ; C264.2 v2(151.76,145.92) ; v2(166.12,60.5) 165.23,59.61 C454.2 ; C485.1 v2(148.84,47.75) ; C464.2 82.77,57.65 ; R315.1 7.51,51.69 U58.2 6.24,51.7 C476.2 v2(6.22,50.93) ; 162.94,105.49 162.94,106.93 ; 162.94,106.93 161.49,106.93 ; 162.94,106.93 164.39,106.93 ; 162.94,106.93 162.94,108.38 ; R398.2 13.65,15.87 v2(13.4,16.13) R397.1 ; v2(136.53,60.32) RJ25.1 RJ24.1 ; R423.2 139.48,93.18 v2(139.45,93.22) ; v2(113.59,41.99) 113.59,41.73 C503.2 ; v2(120.4,39.09) 119.63,38.33 C511.2 ; v2(92.05,52.27) 92.04,52.29 C469.2 ; C474.2 88,53.56 ; C474.2 88,51.43 ; C474.2 88.75,52.5 ; 81.76,52.5 C475.2 ; C475.2 82.51,51.43 ; C475.2 82.51,53.56 ; Q11.4 v2(78.22,139.94) ; R195.2 v2(151.38,154.31) ; v2(65.05,100.03) C272.2 v2(65.05,101.85) ; v2(156.59,90.99) 156.73,91.13 P9.12 ; R235.2 v2(37.97,98.55) ; 127.13,39.62 127.13,39.88 v2(126.62,40.39) ; C470.2 78.23,54.6 ; C470.2 78.23,52.84 ; C470.2 77.48,53.72 ; 160.04,49.66 P5.4 ; P5.4 161.54,48.16 ; P5.4 163.04,49.66 ; P5.4 161.54,51.16 ; v2(61.85,100.08) C273.2 v2(61.85,101.85) ; R301.1 v2(13.4,61.85) 13.65,61.59 R302.2 ; v2(87.25,55.12) 87.46,54.91 C467.2 ; v2(64.26,74.09) C391.2 v2(64.24,75.51) ; 82.18,63.63 C441.2 ; X2.2 22.94,43.26 21.26,41.58 X2.4 v2(19.89,41.58) ; 90.97,53.16 C469.2 ; C469.2 93.1,53.16 ; v2(141.88,67.59) 142.11,67.82 C429.2 C410.2 ; v2(55.75,85.85) C328.2 v2(55.75,87.63) ; v5(153.42,50.04) 152.91,49.53 C487.2 ; J6.3 168.02,108.38 ; J6.3 166.57,106.93 ; J6.3 169.47,106.93 ; J6.3 168.02,105.49 ; C435.2 123.55,68.07 v2(123.21,68.41) ; 162.39,65.93 P2.4 161.27,64.81 ; J16.5 43.69,24.11 ; J16.5 45.19,22.61 ; J16.5 43.69,21.11 ; J16.5 42.19,22.61 ; v2(66.48,76.83) C377.2 ; v2(60.27,89.74) C314.2 v2(60.33,88.32) ; C548.2 v2(77.34,152.78) ; R248.1 R244.1 R240.1 v2(142.24,89.41) ; C263.2 v2(155.57,144.02) ; R259.2 v2(133.48,79.5) ; v5(150.37,53.09) 150.11,52.83 C472.2 ; C479.2 149.86,51.56 v5(150.37,51.05) ; 48.77,21.11 J16.4 ; J16.4 48.77,24.11 ; J16.4 47.27,22.61 ; J16.4 50.27,22.61 ; C350.2 v2(36.07,86.99) ; v2(137.16,72.01) RJ17.3 RJ16.3 ; 23.39,18.41 J18.5 ; J18.5 24.89,19.91 ; J18.5 26.39,18.41 ; J18.5 24.89,16.92 ; C515.2 v2(126.11,34.04) ; C467.2 88.18,55.53 ; C467.2 88.18,54.29 ; J19.52 v2(97.48,19.38) ; C299.2 v2(66.48,91.06) ; C291.2 120.4,95.38 v2(121.03,94.74) 121.79,95.5 C290.2 ; C519.2 v2(115.19,33.27) ; v1(91.69,92.97) 91.7,92.96 C296.2 ; C342.2 95.9,86.35 v1(95.89,86.33) ; C500.1 129.42,44.07 v2(129.64,43.85) ; C466.2 152.15,54.36 v5(152.4,54.1) ; v2(6.22,39.5) C504.2 6.24,40.27 U60.2 7.51,40.26 R353.1 ; J19.4 68.69,19.2 v2(68.45,19.43) 68.09,19.07 J19.3 ; J19.109 v2(73.48,11.51) ; C521.2 v2(131.64,29.34) ; 166.62,43.08 P5.3 ; P5.3 166.62,46.08 ; P5.3 165.12,44.58 ; P5.3 168.12,44.58 ; 83.27,59.02 C447.2 81.14,59.02 ; 87.41,49.08 C481.2 ; U54.2 v2(115.95,64.26) 116.33,64.26 116.6,63.99 U54.3 ; C498.1 v2(137.16,45.78) ; U72.3 78.09,142.22 v2(77.85,141.99) ; v2(65.1,85.9) C326.2 v2(65.07,87.58) ; v2(163.32,55.58) 164.21,56.46 C462.2 ; R380.2 155.7,32.51 v5(156.34,33.15) ; R359.1 v2(13.4,38.99) 13.65,38.73 R361.2 ; U67.4 v2(145.8,129.8) ; v2(6.22,16.64) C532.2 6.24,17.41 U64.2 7.51,17.4 R396.1 ; J19.6 v2(69.89,19.47) ; RJ23.1 RJ22.1 RJ21.1 RJ20.1 RJ19.1 v2(134.37,72.39) ; C267.2 v2(117.35,157.92) ; v2(148.48,146.55) 148.47,146.55 148.21,146.81 C261.2 ; C440.2 85.46,63.63 ; C275.1 v2(37.97,97.28) ; C506.2 115.82,40.13 115.95,40.26 v2(115.96,40.26) ; v2(126.62,37.59) 127.13,38.1 127.13,38.35 ; C265.2 v5(89.79,140.97) ; C260.2 v2(151.51,146.81) ; C465.2 77.72,56.5 ; C465.2 76.97,55.63 ; C465.2 77.72,54.75 ; J19.23 v2(80.09,19.38) ; v2(60.52,75.69) C392.2 60.46,74.11 v2(60.46,74.11) ; C370.2 v1(95.24,81.78) C362.2 ; J19.63 v2(101.08,11.51) ; C497.2 v2(106.3,45.59) ; C518.2 v2(117.98,33.27) ; R387.1 v2(13.4,27.56) 13.65,27.3 R390.2 ; C381.2 v2(40.64,80.14) ; P9.16 156.73,89.63 v2(156.59,89.49) ; C458.2 93.24,58.54 v2(93.24,58.55) ; C458.2 91.41,58.54 ; C458.2 92.29,59.29 ; 94.11,81.15 v1(93.94,81.78) ; R343.1 v2(100.58,45.59) ; R375.2 v2(112.27,33.02) ; C507.2 122.2,39.88 v2(121.69,40.39) ; C549.1 v2(29.21,139.06) ; J19.28 83.09,19.21 83.31,19.43 v2(83.31,19.46) ; C514.2 v2(133.73,34.04) ; 166.57,112.01 J6.2 ; J6.2 169.47,112.01 ; J6.2 168.02,113.46 ; J6.2 168.02,110.57 ; R330.2 v2(120.14,46.86) ; v2(78.23,83.19) 78.74,83.69 C282.2 ; P10.6 v2(153.01,128.17) ; v1(96.54,81.13) C357.2 ; R320.2 v2(32.38,49.78) ; R197.2 v2(146.94,154.31) ; J19.36 v2(87.89,19.43) ; v2(128.21,67.41) 128.52,67.1 C411.2 ; Q11.1 v2(79.52,136.4) ; C505.1 v2(133.73,41.66) ; J19.75 v2(93.88,11.51) ; v5(154.43,51.05) 154.81,50.67 C480.2 ; J19.17 v2(76.48,19.41) ; C353.2 v2(154.81,81.89) ; R386.1 7.51,28.83 U62.2 6.24,28.84 C523.2 v2(6.22,28.07) ; J19.11 v2(72.88,16.78) ; 87.36,63.02 C443.2 86.49,63.77 ; v2(124.02,29.34) C522.2 ; U66.4 v2(145.8,127.26) ; v2(6.22,62.36) C439.2 6.24,63.13 U53.2 7.51,63.12 R294.1 ; R309.1 119.38,52.96 v2(119,52.58) ; P9.44 v2(161.04,81.15) P9.43 v2(161.04,87.38) P9.42 v2(161.04,93.66) P9.41 ; R322.2 v2(133.48,48.13) ; U71.3 v2(77.96,148.48) ; C258.2 v2(92.08,164.59) ; R207.2 v2(93.47,146.56) ; C433.2 v2(123.82,71.88) ; R205.2 v2(157.23,146.75) ; R401.2 v2(73.66,122.68) ; v2(111.89,83.82) 111.9,83.84 ; J19.93 v2(83.09,11.56) ; R251.2 v2(132.84,83.44) ; J19.118 68.09,11.91 67.94,11.77 v2(67.94,11.05) ; 168.02,92.33 v2(168.78,92.33) ; J19.104 v2(76.48,11.51) ; J19.40 v2(90.29,19.42) ; J19.46 v2(93.88,19.56) ; J19.86 v2(87.29,11.56) ; C478.1 v2(136.91,50.42) ; 156.97,44.96 v2(156.97,44.2)
  BOTTOM w0.381: v4(70.94,84.11) C351.2 v4(70.94,82.8) ; C285.2 C284.2 ; v4(84.38,76.15) C385.2 82.64,74.46 v4(82.54,74.36) ; v1(95.24,88.28) 94.92,88.93 ; C364.2 v1(90.04,82.43) ; v4(70.66,89.38) 71.25,89.38 71.52,89.11 C307.2 71.68,88.21 v4(71.63,88.15) ; v4(81.78,76.15) 81.23,76.7 C380.2 80.18,76.7 79.63,76.15 79.63,76.01 v4(79.57,75.95) ; v4(72.8,82.79) C354.2 v4(72.8,84.09) ; C302.2 v2(103.38,91.13) ; C431.2 v2(113.03,66.17) ; v4(101.92,98.81) 101.28,98.81 C286.2 ; 111.9,83.84 C343.2 ; v2(109.14,91.14) 109.02,91.14 109.02,91.14 C303.2 v2(106.59,91.14) ; v4(69.16,82.78) C352.2 v4(69.16,84.11) ; C428.2 v2(72.77,68.2) ; C406.2 v2(79.5,71.12) ; v1(97.19,89.58) 97.23,89.54 97.91,89.54 97.91,89.54 C306.2 ; C432.2 v2(111.89,66.17) ; C430.2 v2(114.17,66.17) ; v4(111.82,80.14) 111.83,80.15 C372.2 ; C434.2 v2(72.77,66.8) ; C348.2 91.34,83.44 v1(91.34,83.08) ; C374.2 86.55,77.72 v4(85.18,76.36) ; C344.2 v2(106.45,83.81)
  BOTTOM w0.406: v2(104.39,83.06) 104.14,82.81 C358.2 ; v2(25.27,78.36) 24.26,78.36 C397.1 ; C395.2 90.8,73.96 v4(91.11,73.66) 91.13,73.64 C401.2 v4(91.13,71.22) ; v2(111.89,83.82) E4.2 109.16,83.82 v2(109.13,83.79) 109.11,83.81 C344.2 ; v4(85.22,97.68) C289.2 v4(82.68,97.68) ; v2(89.24,73.44) 89.23,73.44 C394.2 ; v4(101.92,98.81) E1.2 v4(104.6,98.81) ; v4(94.67,73.66) C402.2 v4(94.67,71.22) ; v2(25.08,90.74) 24.64,91.19 C317.1 ; v2(109.14,91.14) 109.15,91.12 E2.2 111.93,91.12 v2(111.94,91.14) C301.2 ; v4(103.96,74.24) 103.84,74.24 102.98,75.1 102.98,75.13 v4(102.11,76) C379.2 ; v4(109.09,81.77) 109.06,81.81 C373.2 106.68,81.81 106.64,81.77 v4(106.62,81.77) ; v4(109.09,80.14) E5.2 v4(111.82,80.14) ; v2(106.59,91.14) 106.56,91.11 v2(105.79,91.11) C551.2 103.4,91.11 v2(103.38,91.13) ; C320.2 103.35,87.76 103.76,87.35 v2(103.76,87.25) 103.76,87.12 103.35,86.71 C329.2 ; v4(96.8,71.12) 96.81,71.14 C403.2 96.81,73.65 v4(96.82,73.66) ; v2(106.05,87.49) C323.2 107.4,87.5 v2(109.07,87.5) E3.2 v2(111.86,87.5) 111.87,87.49 C324.2 ; C356.2 88.59,84.38 v1(88.09,84.38) ; C426.2 v2(94.72,67.31) ; C334.2 v2(103.76,84.55) ; C345.2 C333.2 v2(104.78,84.55) ; v4(88.12,73.28) E6.2 88.12,70.5 v4(88.12,70.5) 88.14,70.48 C408.2 ; C407.2 83.69,70.53 v4(83.71,70.55) E7.2 83.71,73.21 v2(83.87,73.37) ; v2(105.54,83.69) 105.54,83.44 C359.2 ; v2(98.93,101.09) C281.2 97.74,100.15 97.28,99.69 C284.2 ; C360.1 24.64,86.49 v2(25.08,86.93) ; C412.2 v2(89.15,67.94)
  BOTTOM w0.508: TP63.1 v2(34.04,117.22) ; TP66.1 v2(60.2,21.59) ; C516.2 v2(69.6,32.26) ; C524.2 v2(69.6,24.76) ; TP64.1 v2(138.94,146.69) ; C442.1 v2(113.92,63.75) ; TP65.1 v2(128.27,52.45) ; C277.2 v2(106.05,100.71) ; C288.2 v2(107.31,99.44)
  BOTTOM w0.635: P1.MTG4 97.82,168.18 ; P1.MTG4 97.82,165.44 ; P1.MTG4 96.44,166.81 ; P1.MTG4 99.19,166.81 ; 111.53,161.91 P1.MTG1 ; P1.MTG1 114.28,161.91 ; P1.MTG1 112.9,160.54 ; P1.MTG1 112.9,163.28 ; 159.11,162.52 J2.G1 ; J2.G1 160.87,160.75 ; J2.G1 160.87,164.28 ; J2.G1 162.64,162.52 ; 8.25,129.95 J4.3 ; J4.3 8.25,133.2 ; J4.3 9.88,131.57 ; J4.3 6.63,131.57 ; C2.2 52.38,164.59 ; C2.2 50.16,162.38 ; C2.2 50.16,166.8 ; C2.2 47.95,164.59 ; 5,155.47 J22.MTG1 ; J22.MTG1 6.96,156.66 ; J22.MTG1 5,157.86 ; J22.MTG1 3.04,156.66 ; 8.25,124.87 J4.4 ; J4.4 9.88,126.49 ; J4.4 8.25,128.12 ; J4.4 6.63,126.49 ; P1.MTG3 114.88,166.81 ; P1.MTG3 113.51,165.44 ; P1.MTG3 113.51,168.18 ; P1.MTG3 112.14,166.81 ; J1.G1 140.03,162.52 ; J1.G1 136.5,162.52 ; J1.G1 138.27,164.28 ; J2.G2 147.74,164.28 ; J2.G2 149.5,162.52 ; J2.G2 145.97,162.52 ; C65.2 28.7,114.35 ; C65.2 30.91,112.14 ; C65.2 26.49,112.14 ; C65.2 28.7,109.93 ; J2.7 154.31,159.88 ; J2.7 154.31,158.15 ; J2.7 153.44,159.02 ; J2.7 155.17,159.02 ; 149.94,160.52 J2.4 ; J2.4 151.67,160.52 ; J2.4 150.8,161.38 ; J1.G2 125.13,164.28 ; J1.G2 123.36,162.52 ; J1.G2 126.89,162.52 ; 87.53,155.32 J20.3 ; J20.3 88.65,156.44 ; J20.3 88.65,154.2 ; J20.3 89.76,155.32 ; P1.MTG2 99.8,161.91 ; P1.MTG2 98.42,163.28 ; P1.MTG2 98.42,160.54 ; P1.MTG2 97.05,161.91 ; 67.94,162.38 C3.2 ; C3.2 67.94,166.8 ; C3.2 70.16,164.59 ; C3.2 65.73,164.59 ; J22.MTG2 5,166.86 ; J22.MTG2 6.96,165.66 ; J22.MTG2 3.04,165.66 ; J22.MTG2 5,164.47 ; 4.81,161.16 J22.2 ; J22.2 7.19,161.16 ; J22.2 6,163.01 ; J22.2 6,159.32 ; J3.2 81.89,159.38 ; J3.2 80.77,158.27 ; J3.2 80.77,160.5 ; J3.2 79.65,159.38 ; C1.2 32.38,166.8 ; C1.2 30.17,164.59 ; C1.2 32.38,162.38 ; C1.2 34.6,164.59
  vias: v2(1.27,168.27) v2(1.27,165.23) v2(1.27,162.18) v2(1.27,159.13) v2(1.27,156.08) v2(1.27,153.03) v2(1.27,143.89) v2(1.27,140.84) v2(1.27,137.8) v2(1.27,134.75) v2(1.27,131.7) v2(1.27,128.65) v2(1.27,125.6) v2(1.27,122.55) v2(1.27,119.51) v2(1.27,116.46) v2(1.27,113.41) v2(1.27,110.36) v2(1.27,67.69) v2(1.27,64.64) v2(1.27,61.59) v2(1.27,55.5) v2(1.27,52.45) v2(1.27,49.4) v2(1.27,43.31) v2(1.27,40.26) v2(1.27,37.46) v2(1.27,31.11) v2(1.27,28.07) v2(1.27,21.97) v2(1.27,18.92) v2(1.27,15.87) v2(2.79,69.6) v2(4.32,168.27) v2(4.32,110.36) v2(4.32,104.27) v2(4.32,98.17) v2(5.21,121.92) v2(5.21,118.87) v2(7.37,168.27) v2(7.87,11.56) v2(8,121.92) v2(8,118.87) v2(9.14,91.69) v2(9.14,86.61) v2(9.27,81.79) v2(9.27,76.07) v2(10.41,168.27) v2(10.41,110.36) v2(10.41,98.17) v2(12.7,91.57) v2(12.7,86.36) v2(12.7,81.41) v2(12.83,76.07) v2(13.46,168.27) v2(13.97,11.56) v2(15.62,103.12) v2(15.62,101.98) v2(15.62,100.84) v2(16.51,168.27) v2(16.76,103.12) v2(16.76,101.98) v2(16.76,100.84) v2(17.02,11.56) v2(17.91,103.12) v2(17.91,101.98) v2(19.56,168.27) v2(20.45,31.88) v2(21.59,37.21) v2(21.72,36.19) v2(21.72,35.18) v2(21.72,34.16) v2(21.84,38.48) v2(22.61,168.27) v2(22.99,29.72) v2(22.99,28.57) v2(23.11,27.43) v2(23.11,26.29) v2(23.11,25.15) v2(23.11,24) v2(23.37,21.84) v2(23.75,39.75) v2(24.64,21.84) v2(25.15,87.76) v2(25.27,79.25) v2(25.4,15.87) v2(25.53,51.82) v2(25.53,50.55) v2(25.53,49.28) v2(25.53,48.01) v2(25.53,46.74) v2(25.65,168.27) v2(25.65,90.17) v2(25.65,89.41) v2(25.65,38.35) v2(25.65,37.21) v2(25.65,36.07) v2(25.65,34.92) v2(25.65,33.78) v2(25.65,32.64) v2(25.65,31.5) v2(25.65,30.35) v2(25.65,29.21) v2(25.65,28.07) v2(25.65,26.92) v2(25.65,25.78) v2(25.65,24.64) v2(25.78,41.4) v2(25.91,86.99) v2(26.03,78.36) v2(26.16,21.72) v2(26.16,20.45) v2(26.8,88.9) v2(26.8,81.28) v2(26.8,51.82) v2(26.8,50.55) v2(26.8,49.28) v2(26.8,48.01) v2(26.8,46.74) v2(27.43,13.84) v2(28.07,88.9) v2(28.07,81.28) v2(28.07,51.82) v2(28.07,50.55) v2(28.07,49.28) v2(28.07,48.01) v2(28.7,168.27) v2(28.7,37.21) v2(28.7,36.07) v2(28.7,34.92) v2(28.7,33.78) v2(28.7,32.64) v2(28.7,28.19) v2(28.7,27.05) v2(28.7,20.45) v2(28.83,25.91) v2(28.83,24.64) v2(29.34,88.9) v2(29.34,81.28) v2(29.34,51.82) v2(29.34,50.55) v2(29.34,49.28) v2(29.34,48.01) v2(29.34,46.74) v2(29.46,149.22) v2(29.46,15.87) v2(29.64,39.24) v2(29.84,28.45) v2(30.1,24.64) v2(30.23,38.1) v2(30.35,26.92) v2(30.48,35.69) v2(30.48,33.78) v2(30.61,80.77) v2(30.61,51.82) v2(30.61,50.55) v2(30.61,49.28) v2(30.61,48.01) v2(30.61,46.74) v2(30.86,38.99) v2(30.99,149.22) v2(30.99,28.45) v2(30.99,25.53) v2(31.11,30.48) v2(31.62,32.51) v2(31.62,19.81) v2(31.75,168.27) v2(31.75,38.48) v2(31.88,148.21) v2(31.88,146.81) v2(31.88,145.41) v2(31.88,26.42) v2(32,34.04) v2(32,18.41) v2(32.13,22.48) v2(32.51,37.72) v2(32.51,36.58) v2(32.64,35.43) v2(32.64,24.26) v2(33.02,40) v2(33.02,30.1) v2(33.02,28.96) v2(33.02,27.81) v2(33.02,26.67) v2(33.15,31.24) v2(33.27,19.94) v2(33.4,34.67) v2(33.4,33.53) v2(33.4,32.38) v2(33.78,39.24) v2(34.54,38.48) v2(34.8,168.27) v2(34.92,24.64) v2(35.05,19.94) v2(36.32,37.97) v2(36.32,36.58) v2(36.32,21.46) v2(36.58,24.26) v2(36.83,27.18) v2(37.85,168.27) v2(37.85,20.57) v2(38.73,35.56) v2(38.73,27.56) v2(39.24,36.07) v2(39.88,23.75) v2(40.13,29.59) v2(40.13,28.32) v2(40.13,26.03) v2(40.39,41.4) v2(40.39,40.26) v2(40.39,39.24) v2(40.39,38.23) v2(40.77,42.8) v2(40.89,168.27) v2(41.78,33.91) v2(41.78,32.77) v2(41.91,31.62) v2(41.91,30.48) v2(41.91,29.34) v2(41.91,28.19) v2(42.16,26.03) v2(42.54,43.94) v2(43.43,46.48) v2(43.43,26.03) v2(43.56,125.73) v2(43.94,168.27) v2(44.2,20.07) v2(44.45,125.73) v2(44.45,42.54) v2(44.45,41.4) v2(44.45,40.26) v2(44.45,39.12) v2(44.45,37.97) v2(44.45,36.83) v2(44.45,35.69) v2(44.45,34.54) v2(44.45,33.4) v2(44.45,32.26) v2(44.45,31.11) v2(44.45,29.97) v2(44.45,28.83) v2(44.96,25.91) v2(44.96,24.51) v2(45.34,125.73) v2(46.23,18.03) v2(46.61,125.73) v2(46.99,168.27) v2(47.5,125.73) v2(47.5,41.4) v2(47.5,40.26) v2(47.5,39.12) v2(47.5,37.97) v2(47.5,36.83) v2(47.5,32.38) v2(47.5,31.24) v2(47.62,30.1) v2(47.62,28.83) v2(47.62,24.51) v2(48.26,20.07) v2(48.39,125.73) v2(48.43,43.43) v2(48.64,32.64) v2(48.89,28.83) v2(49.02,42.29) v2(49.15,31.11) v2(49.28,125.73) v2(49.28,39.88) v2(49.28,37.97) v2(49.66,43.18) v2(49.78,32.64) v2(49.78,29.72) v2(49.91,34.67) v2(50.04,168.27) v2(50.42,36.7) v2(50.42,24) v2(50.55,126.05) v2(50.55,42.67) v2(50.67,30.61) v2(50.8,38.23) v2(50.8,22.61) v2(51.18,117.86) v2(51.18,116.97) v2(51.18,116.08) v2(51.31,41.91) v2(51.31,40.77) v2(51.43,39.62) v2(51.43,28.45) v2(51.82,44.2) v2(51.82,34.29) v2(51.82,33.15) v2(51.82,32) v2(51.82,30.86) v2(51.94,35.43) v2(52.07,117.86) v2(52.07,116.97) v2(52.07,116.08) v2(52.2,38.86) v2(52.2,37.72) v2(52.2,36.58) v2(52.2,24.13) v2(52.58,125.35) v2(52.58,43.43) v2(52.96,116.97) v2(52.96,116.08) v2(53.09,168.27) v2(53.34,42.67) v2(53.72,28.83) v2(53.85,117.86) v2(53.85,116.97) v2(53.85,116.08) v2(53.85,24.13) v2(54.74,117.86) v2(54.74,116.97) v2(55.12,124.46) v2(55.12,42.29) v2(55.12,40.77) v2(55.12,25.65) v2(55.37,28.45) v2(55.63,31.37) v2(56.13,168.27) v2(56.64,24.76) v2(56.64,11.56) v2(57.4,39.62) v2(57.4,31.75) v2(58.55,28.07) v2(58.8,33.78) v2(58.8,32.51) v2(58.8,30.1) v2(59.18,168.27) v2(59.69,11.56) v2(59.94,125.73) v2(61.72,125.73) v2(62.23,168.27) v2(62.61,125.73) v2(62.74,11.56) v2(63.75,125.73) v2(64.64,125.73) v2(65.28,168.27) v2(65.53,125.73) v2(65.53,124.71) v2(65.79,11.56) v2(68.33,168.27) v2(68.58,125.73) v2(68.58,124.71) v2(69.47,125.73) v2(70.36,125.73) v2(70.36,43.43) v2(70.36,42.42) v2(71.37,168.27) v2(73.03,35.56) v2(73.03,34.29) v2(73.03,28.07) v2(73.03,26.8) v2(73.41,34.92) v2(73.41,27.43) v2(73.79,35.56) v2(73.79,34.29) v2(73.79,28.07) v2(73.79,26.8) v2(74.42,168.27) v2(75.69,130.05) v2(77.47,168.27) v2(78.61,125.73) v2(78.61,124.21) v2(80.14,125.73) v2(80.14,124.21) v2(82.91,81.02) v2(83.19,116.71) v2(83.19,58.17) v2(83.19,57.15) v2(83.19,56.13) v2(83.19,54.1) v2(83.31,117.47) v2(83.44,115.95) v2(83.95,37.08) v2(84.07,117.47) v2(84.1,116.74) v2(84.2,115.19) v2(84.2,58.17) v2(84.2,57.15) v2(84.2,56.13) v2(84.2,55.12) v2(84.2,54.1) v2(84.71,37.08) v2(85.22,58.17) v2(85.22,57.15) v2(85.22,56.13) v2(85.22,55.12) v2(85.22,54.1) v2(86.11,37.08) v2(86.23,58.17) v2(86.23,57.15) v2(86.23,56.13) v2(86.23,55.12) v2(86.23,54.1) v2(86.87,37.08) v2(87.25,58.17) v2(87.25,57.15) v2(87.25,54.1) v2(87.88,151.26) v2(87.88,149.1) v2(87.88,147.95) v2(87.88,146.69) v2(87.88,145.67) v2(87.88,37.46) v2(87.88,36.7) v2(89.66,35.94) v2(89.92,32.51) v2(91.19,27.56) v2(91.44,25.78) v2(92.71,168.27) v2(93.47,124.08) v2(93.47,123.32) v2(94.74,123.7) v2(94.74,122.81) v2(94.74,121.67) v2(94.74,120.78) v2(94.74,119.63) v2(94.74,118.75) v2(94.74,117.6) v2(94.74,116.71) v2(94.74,115.82) v2(95.76,168.27) v2(97.03,151.76) v2(97.16,154.18) v2(98.55,103) v2(98.93,157.73) v2(99.95,149.61) v2(100.08,152.02) v2(100.33,159.26) v2(101.85,168.27) v2(101.85,100.97) v2(102.11,159.26) v2(103.25,70.48) v2(103.63,159.26) v2(103.63,151.64) v2(103.76,149.61) v2(103.76,115.57) v2(104.39,69.34) v2(104.78,115.57) v2(104.9,168.27) v2(105.16,159.26) v2(107.19,158.62) v2(107.19,151.89) v2(107.31,149.61) v2(107.95,168.27) v2(108.46,157.48) v2(109.09,96.9) v2(109.98,149.61) v2(110.11,154.31) v2(111,168.27) v2(112.9,93.85) v2(114.55,11.56) v2(117.09,168.27) v2(117.35,150.11) v2(117.35,143.13) v2(117.6,11.56) v2(119.1,40.39) v2(120.14,168.27) v2(120.4,41.68) v2(120.4,40.39) v2(123.19,168.27) v2(124.97,148.72) v2(126.24,168.27) v2(126.75,155.32) v2(127.51,155.32) v2(129.29,168.27) v2(129.67,154.05) v2(131.7,145.92) v2(132.33,168.27) v2(133.6,153.92) v2(134.49,149.35) v2(134.75,145.8) v2(134.87,109.73) v2(135.38,168.27) v2(136.27,121.92) v2(136.27,120.65) v2(136.27,119.38) v2(136.27,118.11) v2(136.27,116.84) v2(136.27,115.57) v2(136.27,113.03) v2(136.27,111.12) v2(136.27,109.85) v2(136.27,108.58) v2(136.27,107.31) v2(136.27,106.17) v2(136.27,104.52) v2(136.27,103.5) v2(136.53,101.85) v2(137.54,101.6) v2(138.43,168.27) v2(138.56,101.6) v2(139.29,67.59) v2(139.29,66.29) v2(139.29,65) v2(139.45,101.6) v2(140.08,118.11) v2(140.08,116.84) v2(140.08,115.57) v2(140.08,114.3) v2(140.08,113.03) v2(140.08,111.76) v2(140.08,110.49) v2(140.08,109.22) v2(140.08,107.95) v2(140.08,106.68) v2(140.08,105.41) v2(140.34,101.6) v2(140.59,66.29) v2(141.35,121.92) v2(141.35,118.11) v2(141.35,116.84) v2(141.35,110.49) v2(141.35,109.22) v2(141.48,168.27) v2(141.88,66.29) v2(141.88,65) v2(142.62,121.92) v2(142.62,118.11) v2(142.62,116.84) v2(142.62,110.49) v2(142.62,109.22) v2(142.58,100.97) v2(143.89,121.92) v2(143.89,118.11) v2(143.89,116.84) v2(143.89,110.49) v2(143.89,109.22) v2(144.02,100.97) v2(144.53,168.27) v2(145.16,121.92) v2(145.16,118.11) v2(145.16,116.84) v2(145.16,110.49) v2(145.16,109.22) v2(145.16,101.09) v2(146.43,118.11) v2(146.43,116.84) v2(146.43,115.57) v2(146.43,114.3) v2(146.43,113.03) v2(146.43,111.76) v2(146.43,110.49) v2(146.43,109.22) v2(146.43,107.95) v2(146.43,106.68) v2(146.43,105.41) v2(146.43,101.09) v2(147.07,133.99) v2(147.07,131.44) v2(147.07,128.91) v2(147.57,168.27) v2(147.57,101.09) v2(147.7,121.92) v2(147.7,118.11) v2(147.7,116.84) v2(147.7,110.49) v2(147.7,109.22) v2(148.84,122.43) v2(148.97,116.84) v2(148.97,110.49) v2(148.97,109.22) v2(148.97,101.47) v2(149.99,122.43) v2(150.24,116.84) v2(150.24,109.22) v2(150.62,168.27) v2(150.75,100.97) v2(151.51,118.11) v2(151.51,116.84) v2(151.51,110.49) v2(151.51,109.22) v2(151.76,122.81) v2(152.78,122.68) v2(152.78,118.11) v2(152.78,116.84) v2(152.78,115.57) v2(152.78,114.3) v2(152.78,113.03) v2(152.78,111.76) v2(152.78,110.49) v2(152.78,109.22) v2(152.78,107.95) v2(152.78,106.68) v2(152.78,105.41) v2(152.78,100.84) v2(153.16,131.7) v2(153.67,168.27) v2(154.05,122.55) v2(154.05,118.11) v2(154.05,116.84) v2(154.05,115.57) v2(154.05,114.3) v2(154.05,113.03) v2(154.05,111.76) v2(154.05,110.49) v2(154.05,109.22) v2(154.05,107.95) v2(154.05,106.68) v2(154.05,105.41) v2(154.56,133.73) v2(154.81,100.84) v2(155.32,121.92) v2(155.32,118.11) v2(155.32,116.84) v2(155.32,115.57) v2(155.32,114.3) v2(155.32,113.03) v2(155.32,111.76) v2(155.32,110.49) v2(155.32,109.22) v2(155.32,107.95) v2(155.32,106.68) v2(155.32,105.41) v2(156.59,121.92) v2(156.59,118.11) v2(156.59,116.84) v2(156.59,115.57) v2(156.59,114.3) v2(156.59,113.03) v2(156.59,111.76) v2(156.59,110.49) v2(156.59,109.22) v2(156.59,107.95) v2(156.59,106.68) v2(156.59,105.41) v2(156.72,168.27) v2(156.72,100.84) v2(156.97,18.54) v2(156.97,17.4) v2(156.97,16.26) v2(157.23,11.56) v2(157.86,121.92) v2(157.86,21.21) v2(158.24,100.84) v2(158.24,18.54) v2(158.24,17.4) v2(158.24,16.26) v2(158.75,103.38) v2(158.88,21.21) v2(159.13,121.28) v2(159.51,102.62) v2(159.51,101.09) v2(159.64,109.22) v2(159.64,107.31) v2(159.64,106.17) v2(159.64,104.14) v2(159.77,120.01) v2(159.77,116.84) v2(160.27,21.21) v2(160.4,118.75) v2(160.4,114.3) v2(161.04,113.03) v2(161.04,111.76) v2(161.04,110.49) v2(161.16,21.21) v2(161.29,101.73) v2(161.29,100.58) v2(161.67,118.75) v2(161.67,114.94) v2(162.43,99.95) v2(162.81,168.27) v2(162.94,118.75) v2(162.94,114.94) v2(163.19,101.85) v2(163.83,99.95) v2(164.21,118.11) v2(164.21,114.94) v2(164.47,101.85) v2(164.72,107.44) v2(165.1,99.95) v2(165.48,118.11) v2(165.48,114.94) v2(165.74,101.85) v2(165.86,168.27) v2(165.86,126.87) v2(166.24,107.44) v2(166.37,99.95) v2(166.75,118.11) v2(166.75,114.94) v2(167,101.85) v2(167.64,99.95) v2(168.02,118.11) v2(168.02,114.94) v2(168.02,113.66) v2(168.02,104.78) v2(168.02,103.5) v2(168.27,101.85) v2(168.53,99.06) v2(168.53,97.79) v2(168.78,122.68) v2(168.91,168.27) v2(168.91,166.5) v2(168.91,163.45) v2(168.91,160.4) v2(168.91,157.35) v2(168.91,154.31) v2(168.91,151.26) v2(168.91,145.16) v2(168.91,142.11) v2(168.91,139.06) v2(168.91,136.02) v2(168.91,132.97) v2(168.91,129.92) v2(168.91,23.24) v2(168.91,20.19) v2(168.91,17.14) v2(169.04,117.73) v2(169.04,115.95) v2(169.42,101.47) v2(170.05,122.68) v2(170.05,94.61) v2(170.18,100.58) v2(170.18,95.76) v2(170.31,117.73) v2(170.31,115.95) v2(170.43,99.44) v2(170.43,98.17) v2(170.43,96.9) v2(171.32,122.05) v2(171.32,120.78) v2(171.32,119.51) v2(171.45,117.73) v2(171.45,115.95) v2(171.45,114.68) v2(171.45,113.41) v2(171.45,112.14) v2(171.45,110.87) v2(171.45,108.33) v2(171.45,107.06) v2(171.45,105.79) v2(171.45,104.52) v2(171.45,103.25) v2(171.45,101.98) v2(171.45,100.58) v3(68.53,42.04) v3(69.39,42.04) v3(89.66,34.98) v3(89.66,34.11) v3(92.15,27.56) v3(93.01,27.56) v3(103.38,117.4) v3(103.38,116.54) v3(138.3,17.14) v3(138.3,15.87) v3(138.94,18.41) v3(138.94,14.6) v3(139.57,17.14) v3(139.57,15.87) v3(140.34,37.72) v3(140.34,31.37) v3(140.97,36.45) v3(140.97,35.18) v3(140.97,33.91) v3(140.97,32.64) v3(142.24,35.18) v3(142.24,33.91) v3(145.29,17.14) v3(145.29,15.87) v3(146.56,18.41) v3(146.56,17.14) v3(146.56,15.87) v3(146.56,14.6) v3(147.19,19.68) v3(147.95,35.18) v3(147.95,33.91) v3(147.95,14.6) v3(148.59,36.45) v3(148.59,32.64) v3(149.22,35.18) v3(149.22,33.91) v3(157.35,131.37) v3(157.35,130.51) v5(45.59,53.09) v5(45.59,52.07) v5(45.59,51.05) v5(45.59,50.04) v5(45.59,49.02) v5(46.61,53.09) v5(46.61,52.07) v5(46.61,51.05) v5(46.61,50.04) v5(46.61,49.02) v5(47.62,53.09) v5(47.62,52.07) v5(47.62,51.05) v5(47.62,50.04) v5(47.62,49.02) v5(48.64,53.09) v5(48.64,52.07) v5(48.64,51.05) v5(48.64,50.04) v5(48.64,49.02) v5(49.66,53.09) v5(49.66,52.07) v5(49.66,51.05) v5(49.66,50.04) v5(49.66,49.02) v5(62.1,50.16) v5(62.1,49.15) v5(62.86,49.66) v5(63.63,50.16) v5(63.63,49.15) v5(89.79,143.51) v5(89.79,142.24) v5(91.06,143.51) v5(91.06,142.24) v5(91.06,140.97) v5(92.33,143.51) v5(92.33,142.24) v5(92.33,140.97) v5(93.6,143.51) v5(93.6,142.24) v5(93.6,140.97) v5(141.22,17.27) v5(142.49,17.27) v5(142.49,16) v5(143.76,35.05) v5(143.76,33.78) v5(143.76,17.27) v5(143.76,16) v5(145.03,35.05) v5(145.03,33.78) v5(146.3,33.78) v5(150.37,54.1) v5(150.37,52.07) v5(150.37,50.04) v5(151.38,54.1) v5(151.38,53.09) v5(151.38,52.07) v5(151.38,51.05) v5(152.4,53.09) v5(152.4,52.07) v5(152.4,51.05) v5(152.4,50.04) v5(153.42,54.1) v5(153.42,53.09) v5(153.42,52.07) v5(153.42,51.05) v5(153.8,34.42) v5(153.8,33.15) v5(154.43,54.1) v5(154.43,52.07) v5(155.07,34.42) v5(155.07,33.15) v5(156.34,34.42) v5(157.61,35.69) v5(157.61,34.42) v5(157.61,33.15)
